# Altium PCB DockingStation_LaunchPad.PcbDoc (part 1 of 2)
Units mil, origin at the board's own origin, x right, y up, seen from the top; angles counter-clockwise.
Board outline 5425 x 6950 mil, 4 copper layers (Top Layer, GND, Power, Bottom Layer), stack 58.4 mil thick; 172 components, 183 nets, 692 pads, 746 vias.
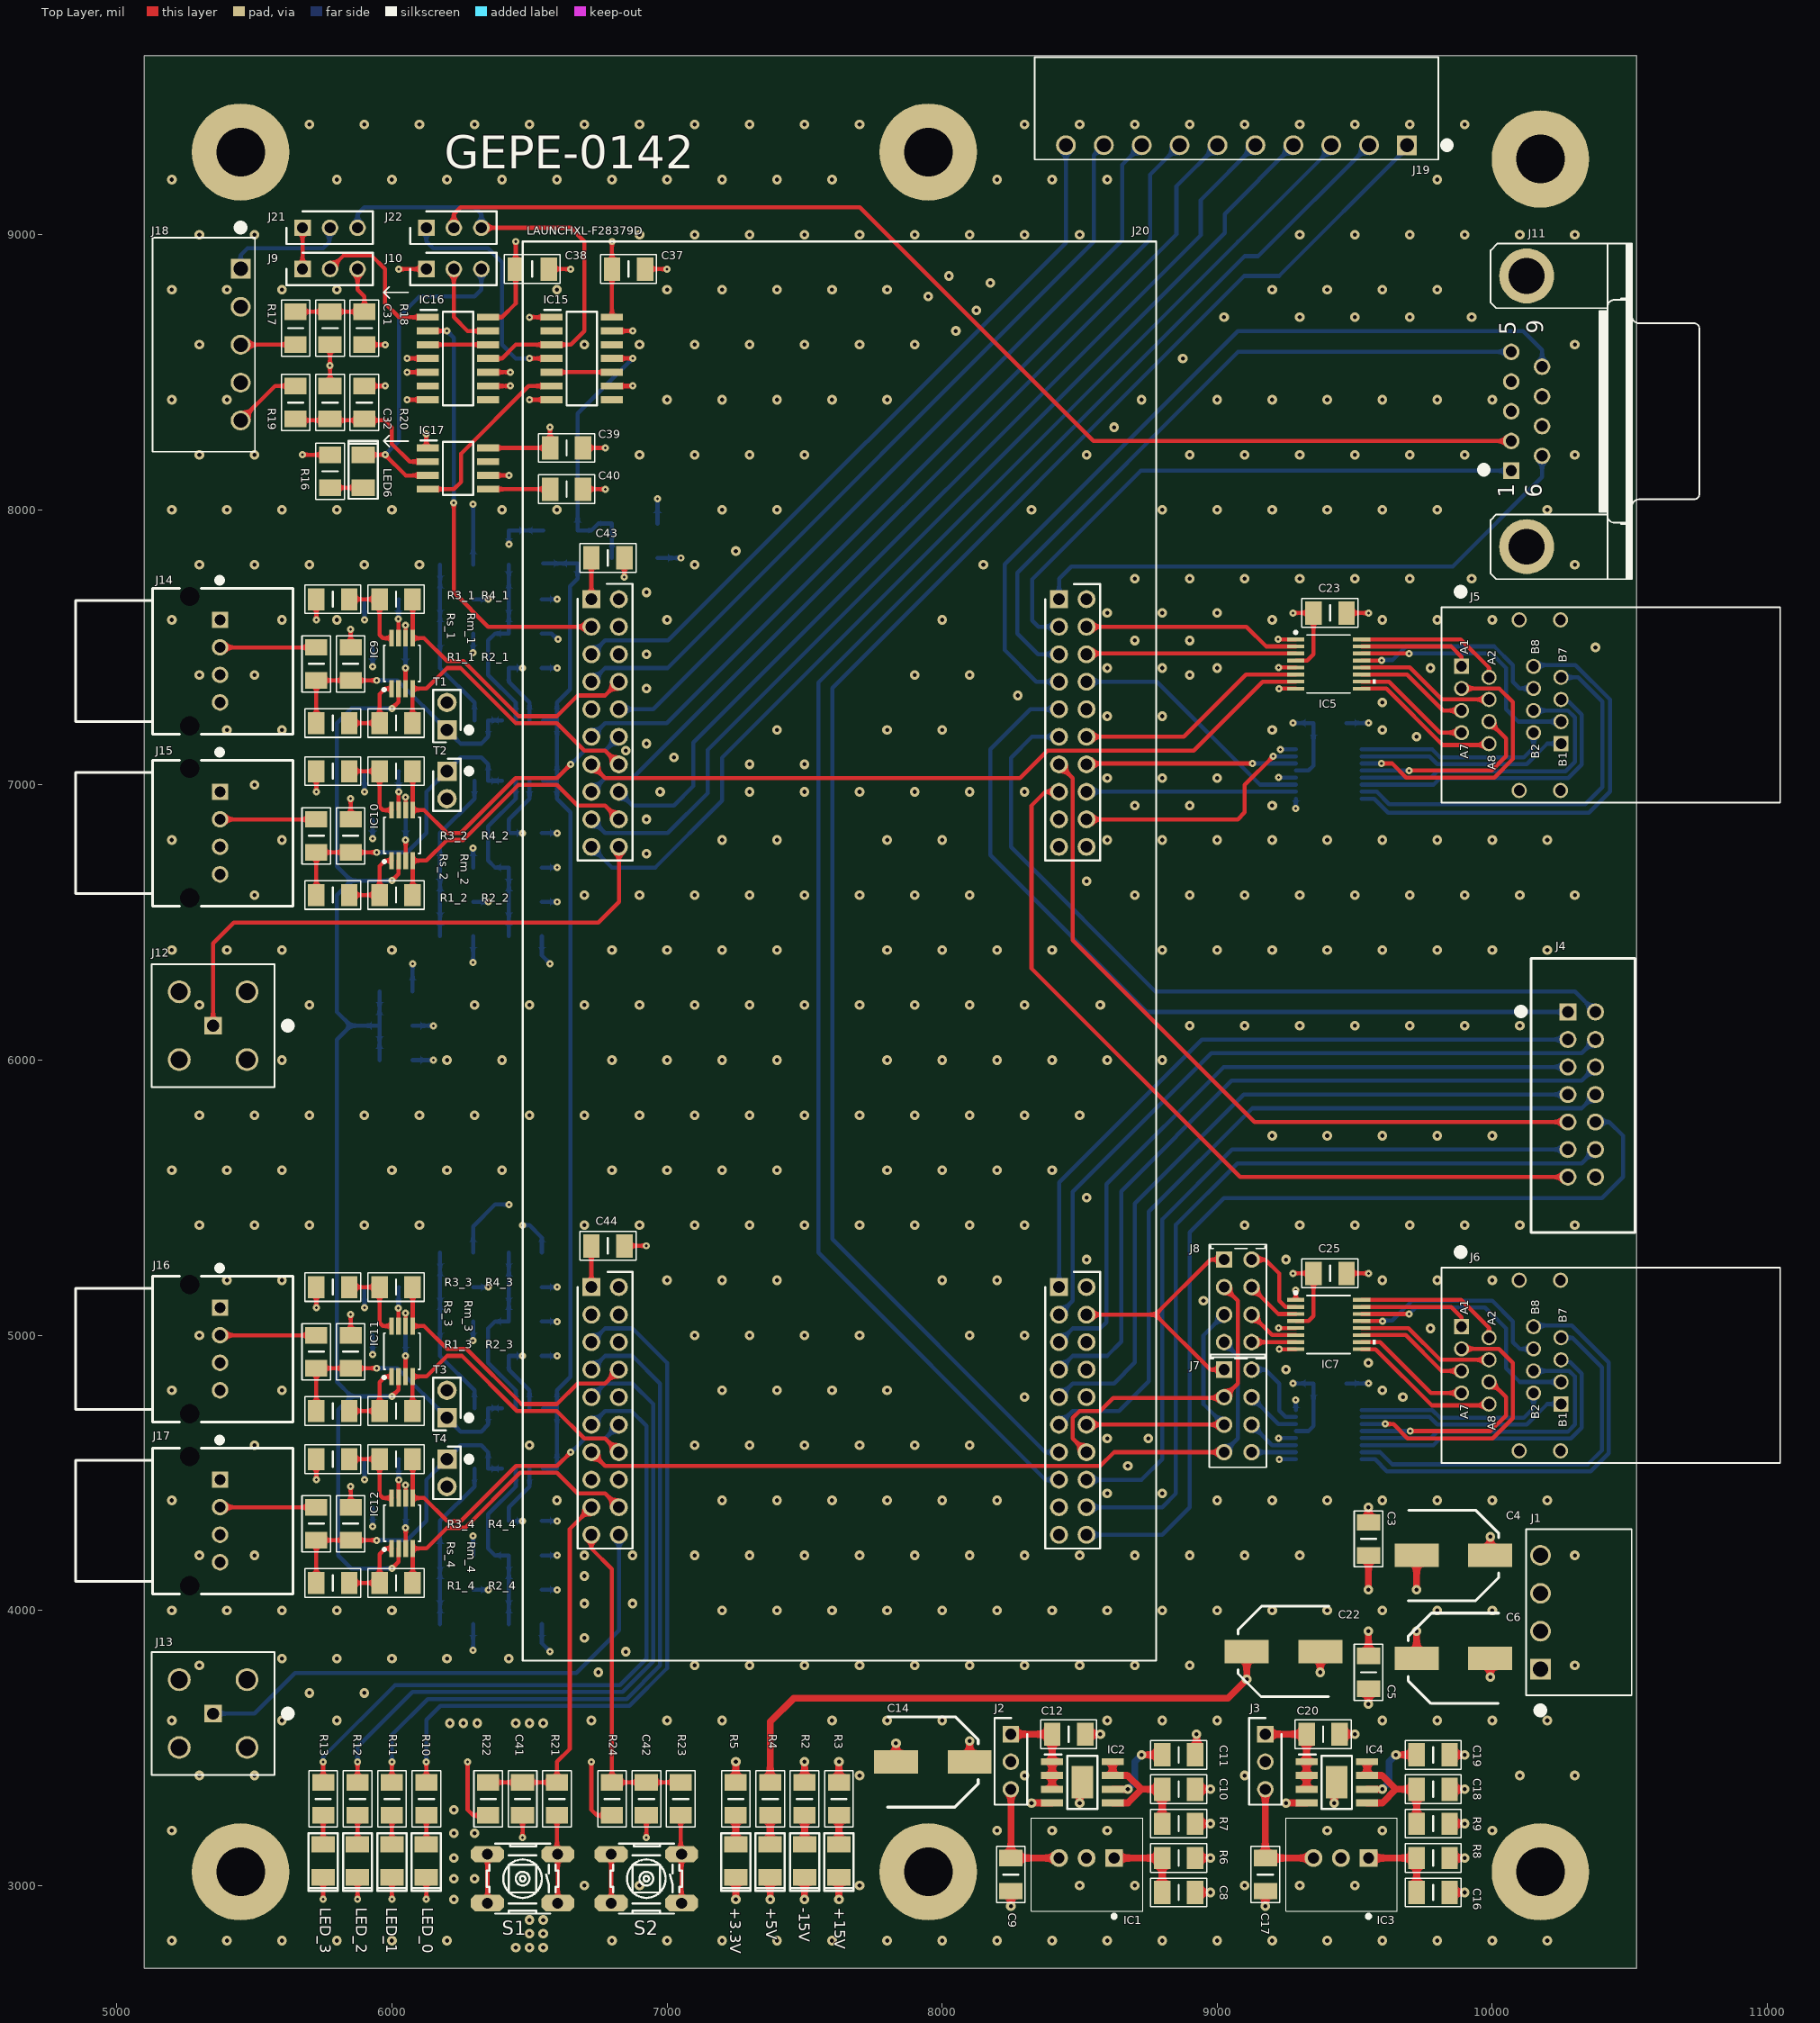
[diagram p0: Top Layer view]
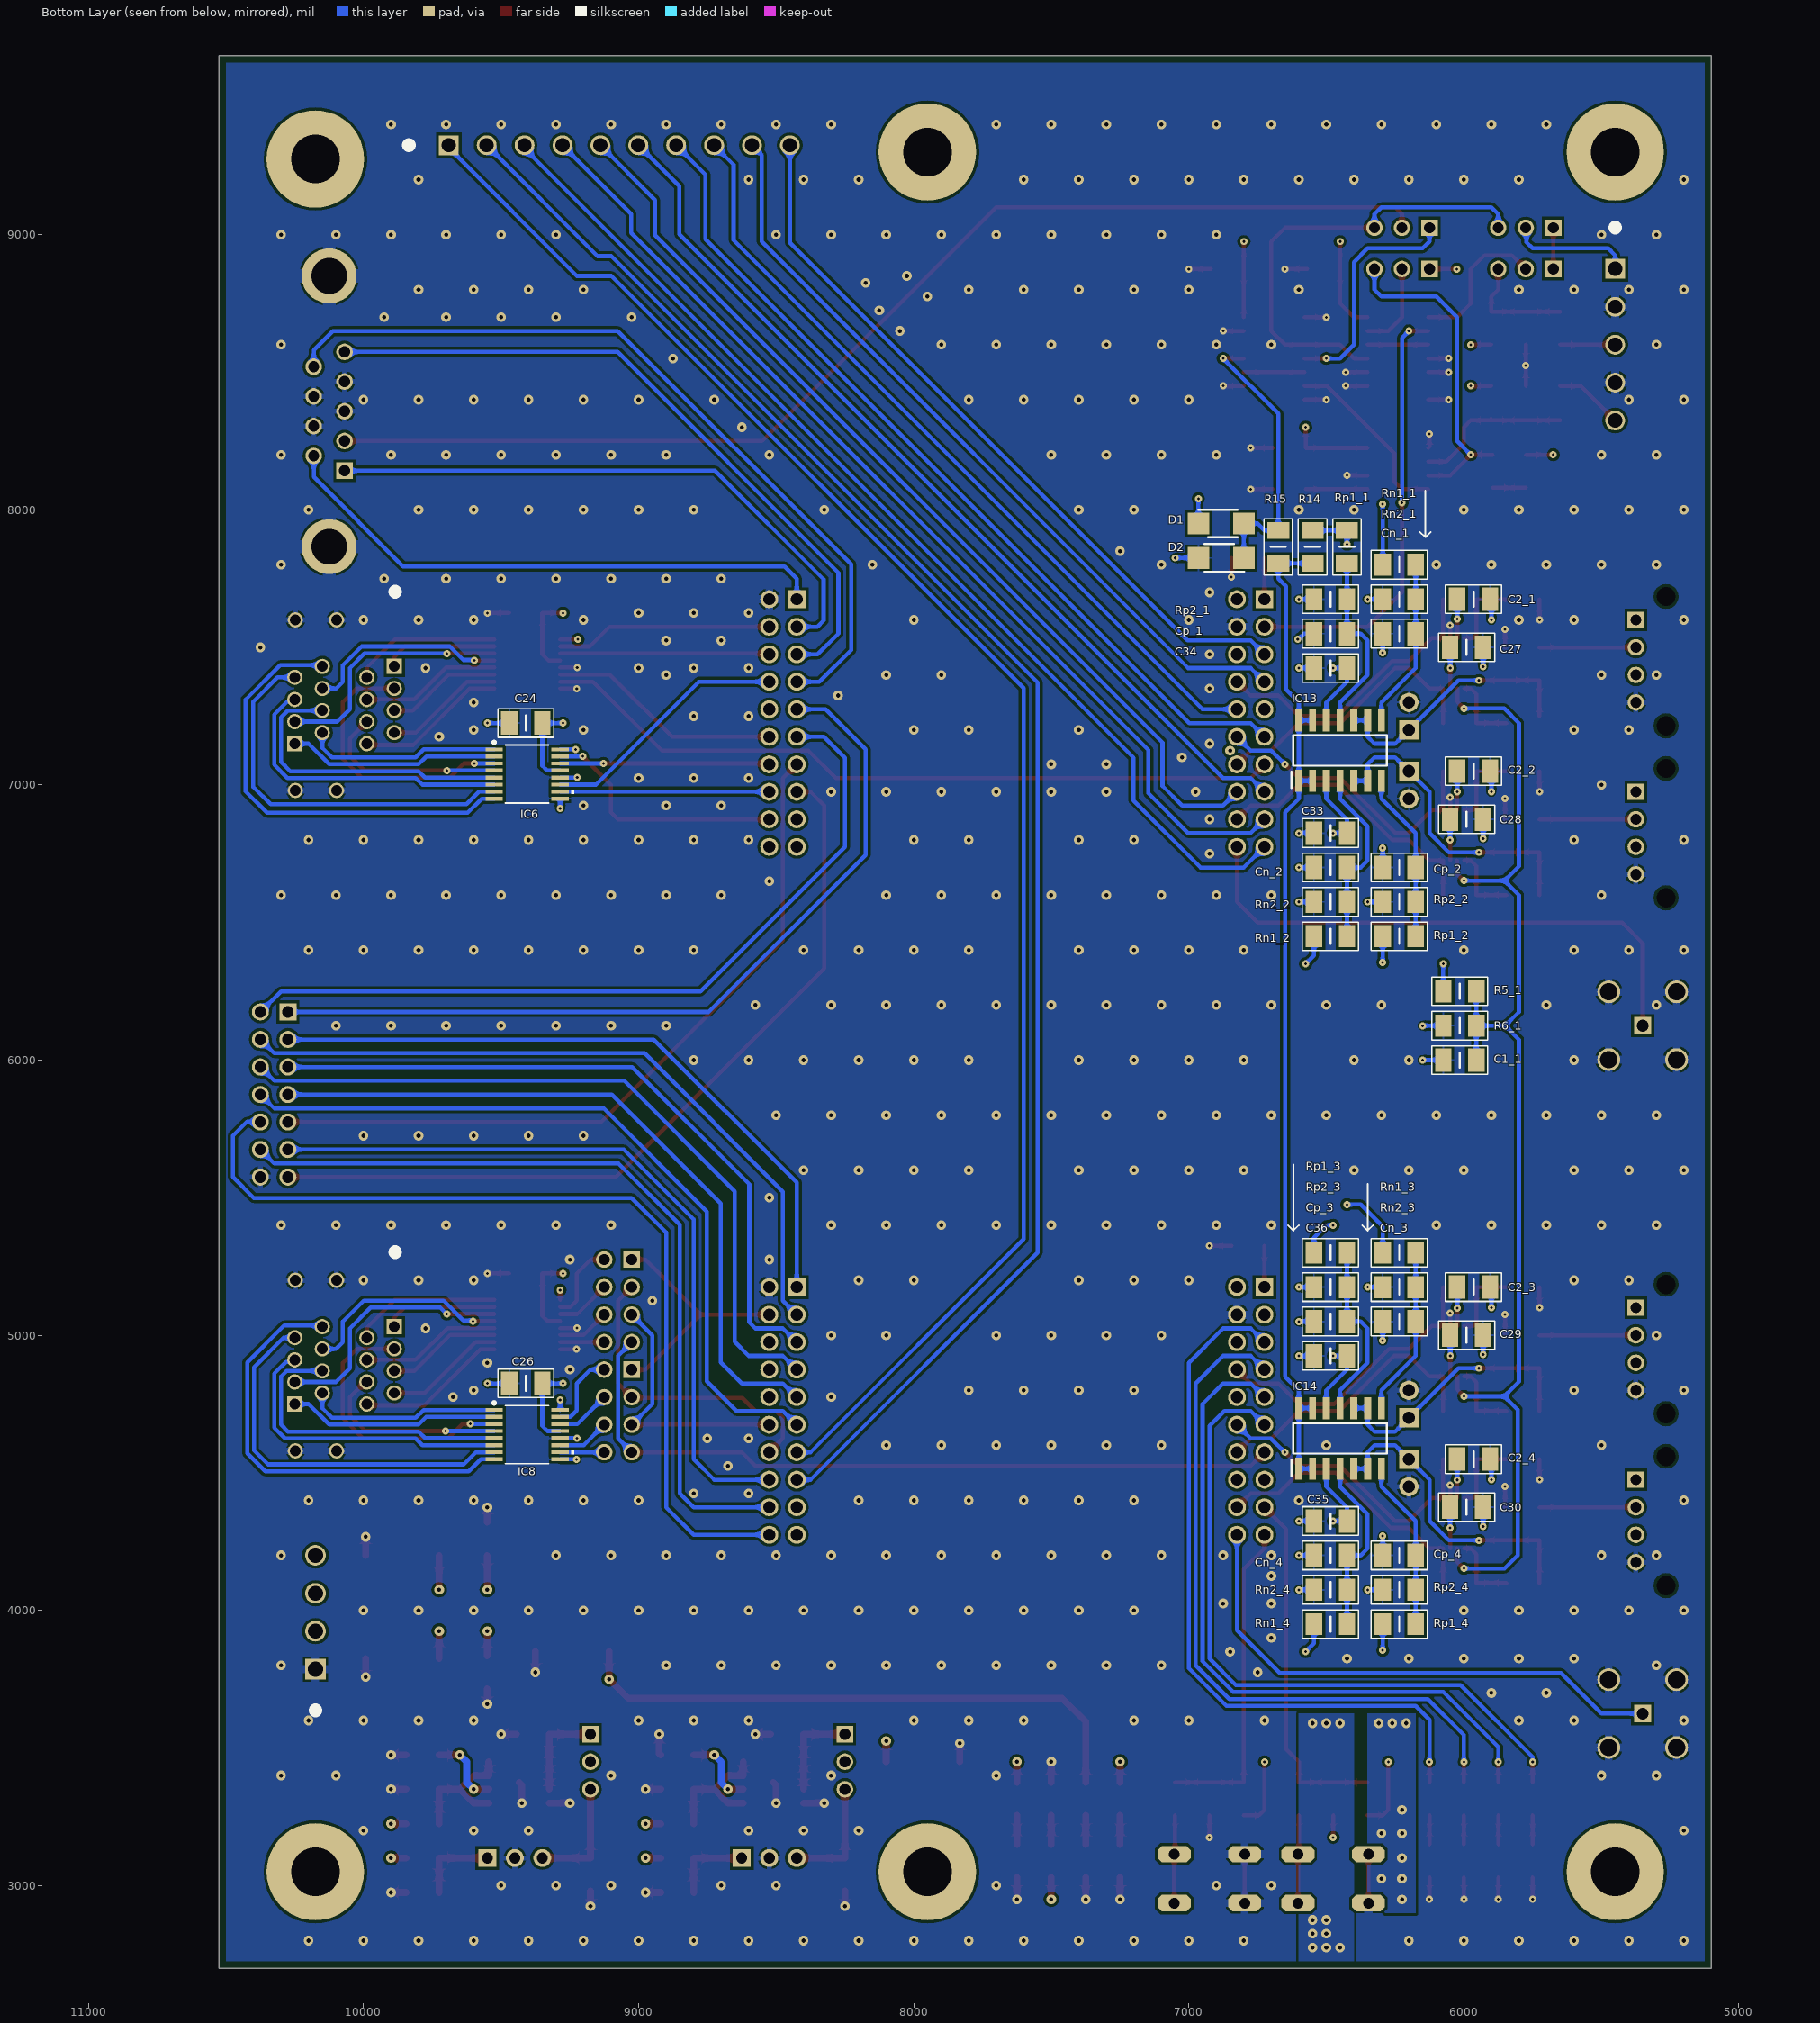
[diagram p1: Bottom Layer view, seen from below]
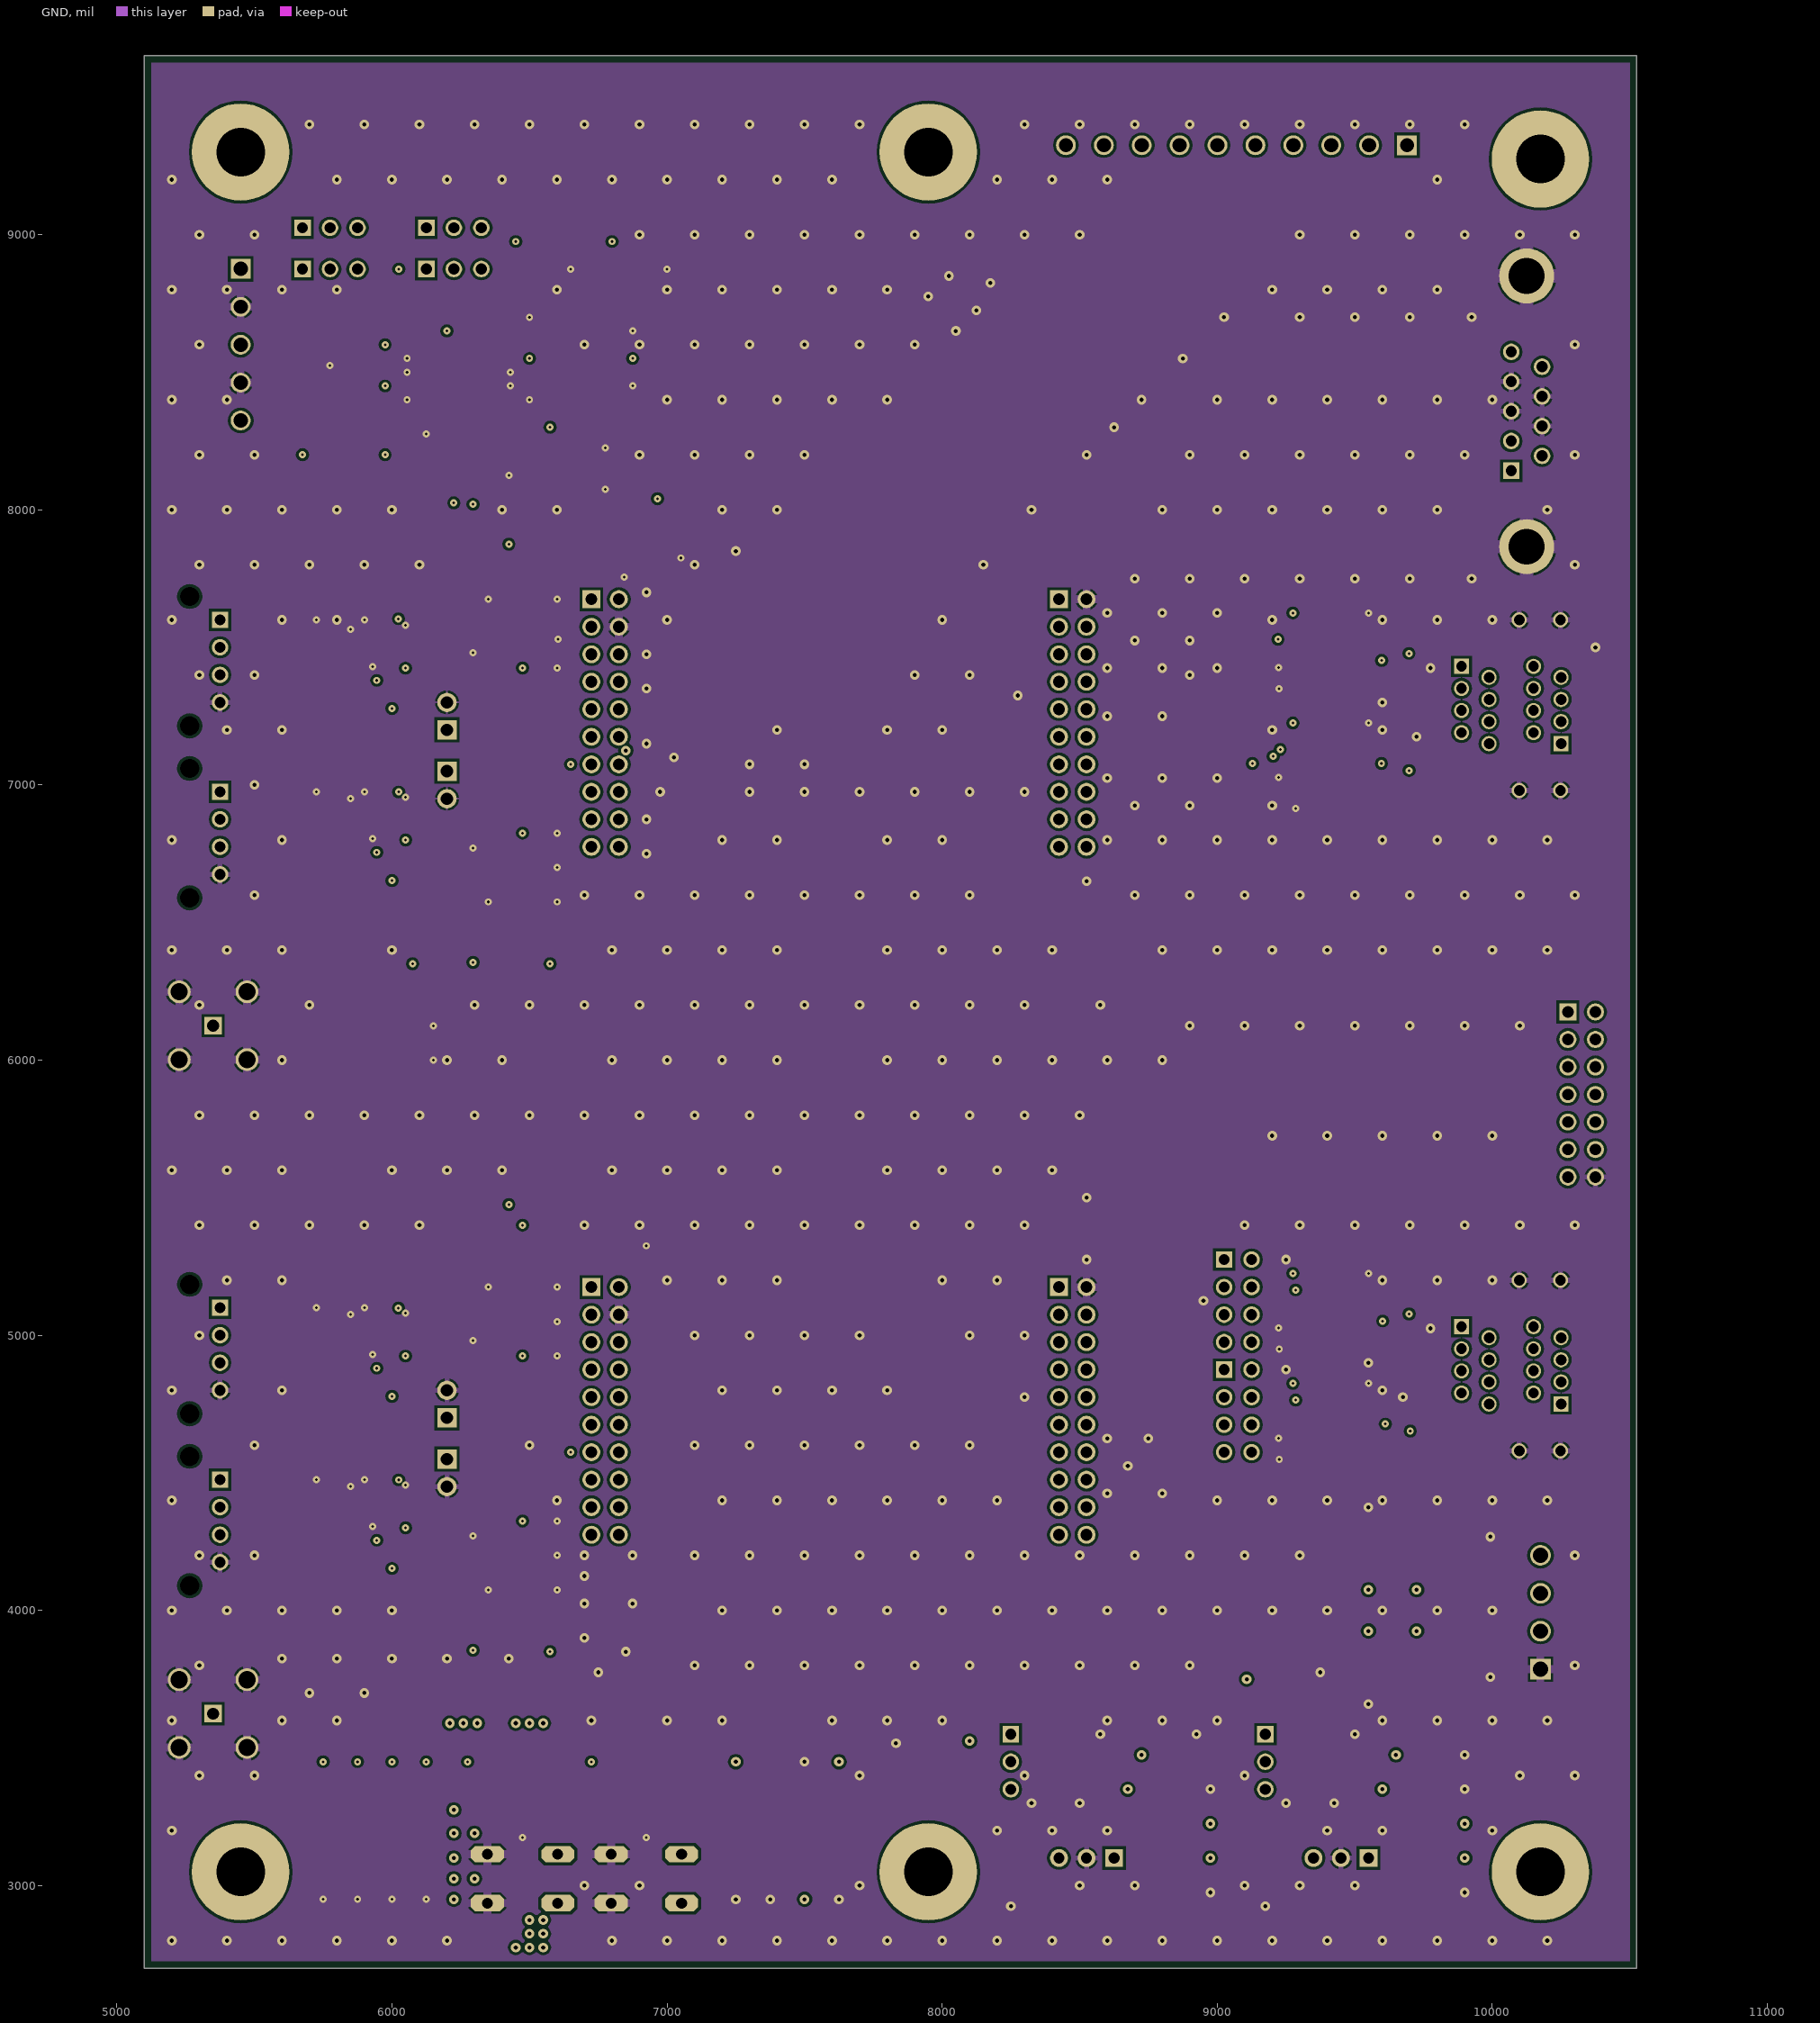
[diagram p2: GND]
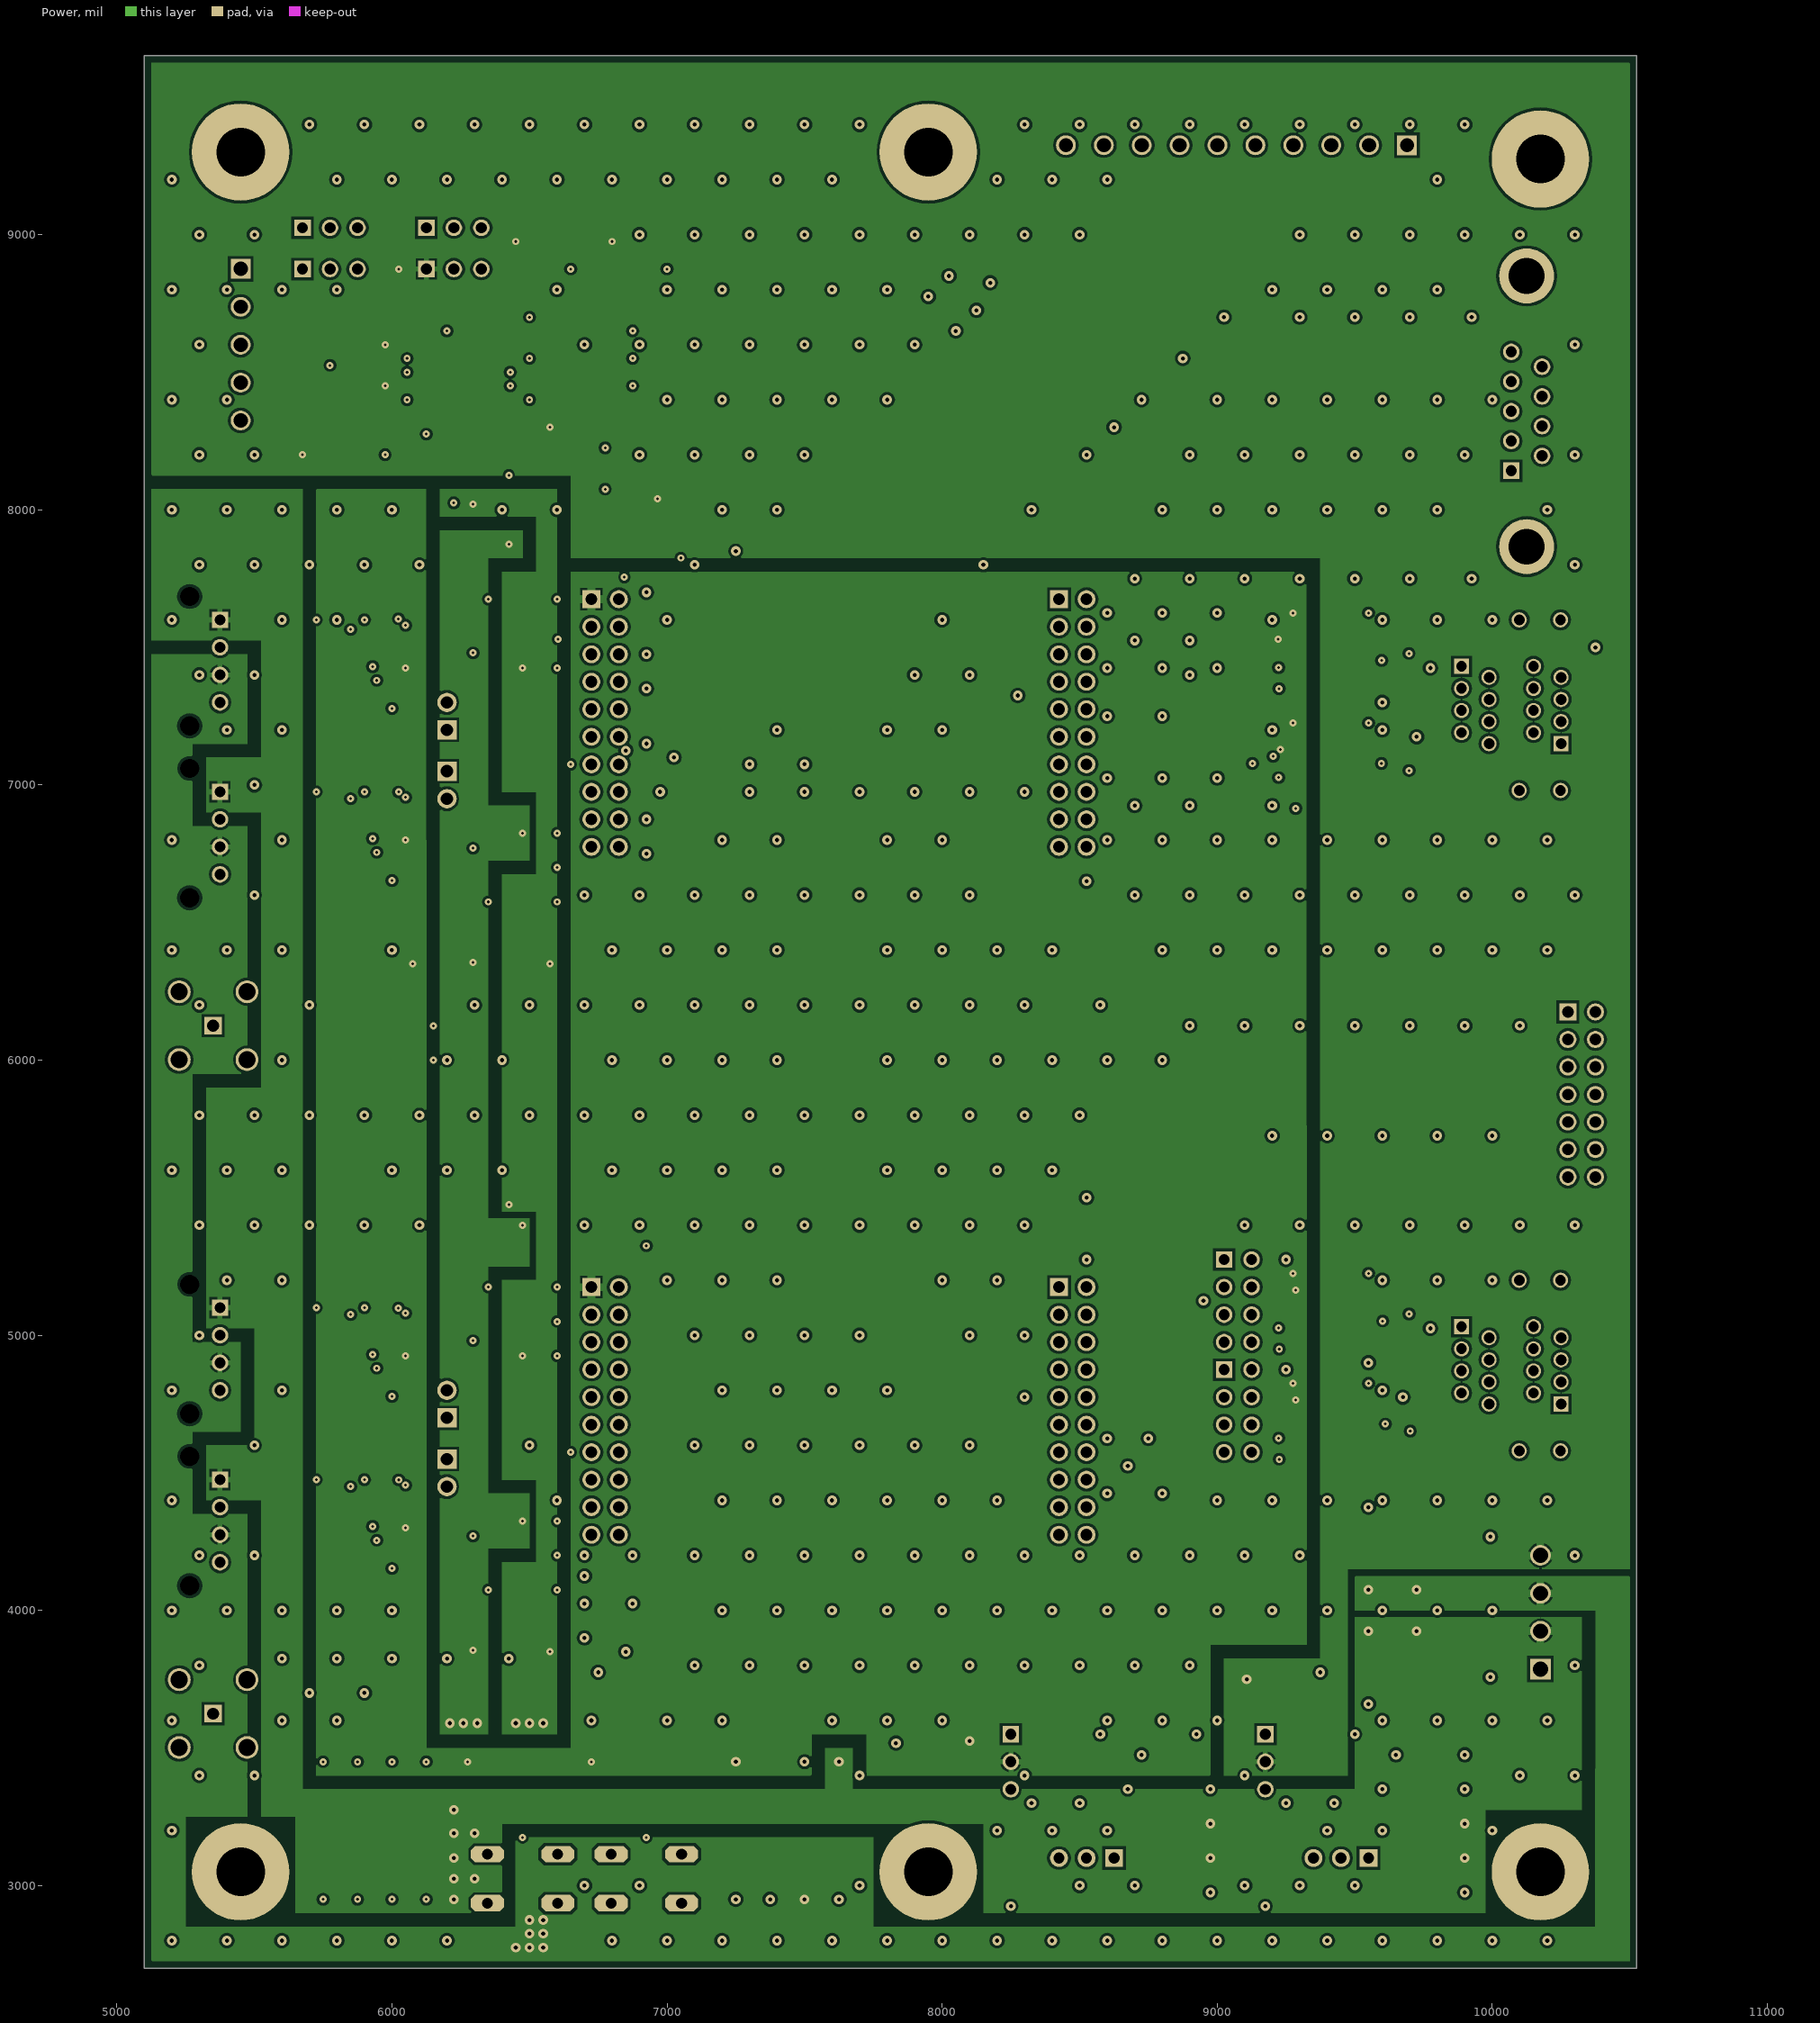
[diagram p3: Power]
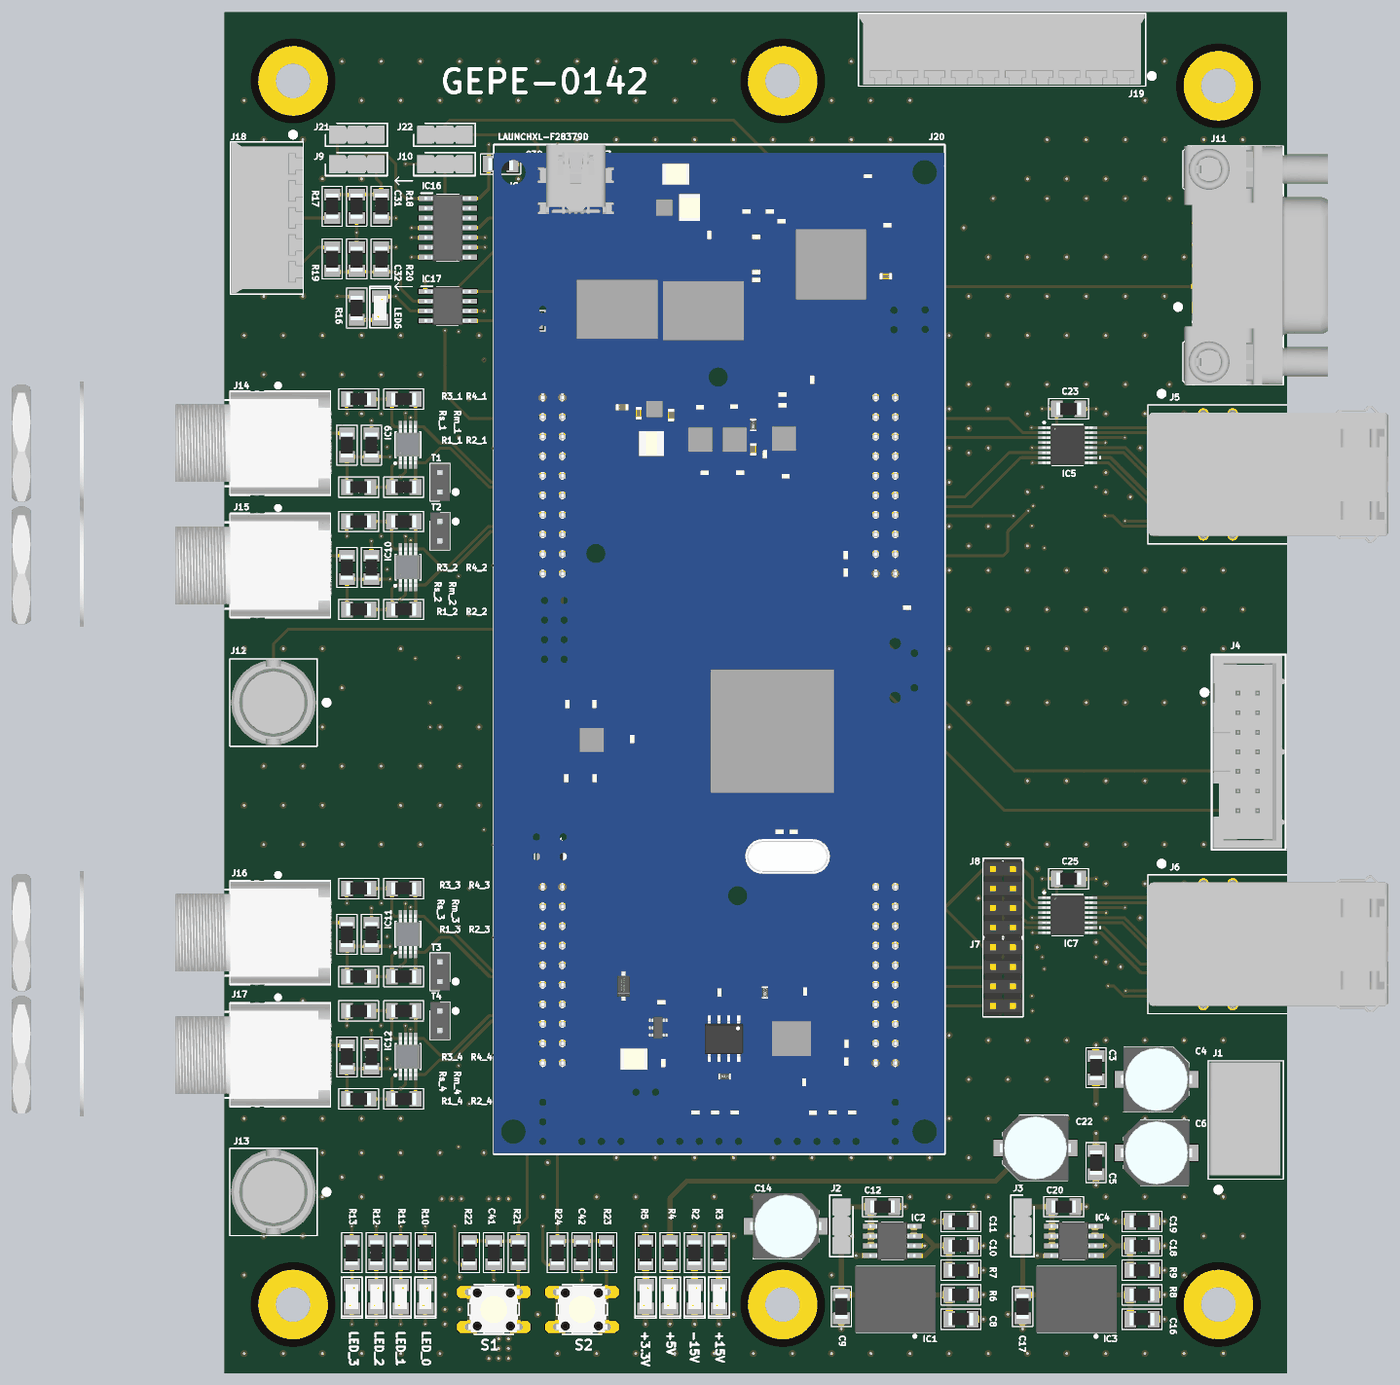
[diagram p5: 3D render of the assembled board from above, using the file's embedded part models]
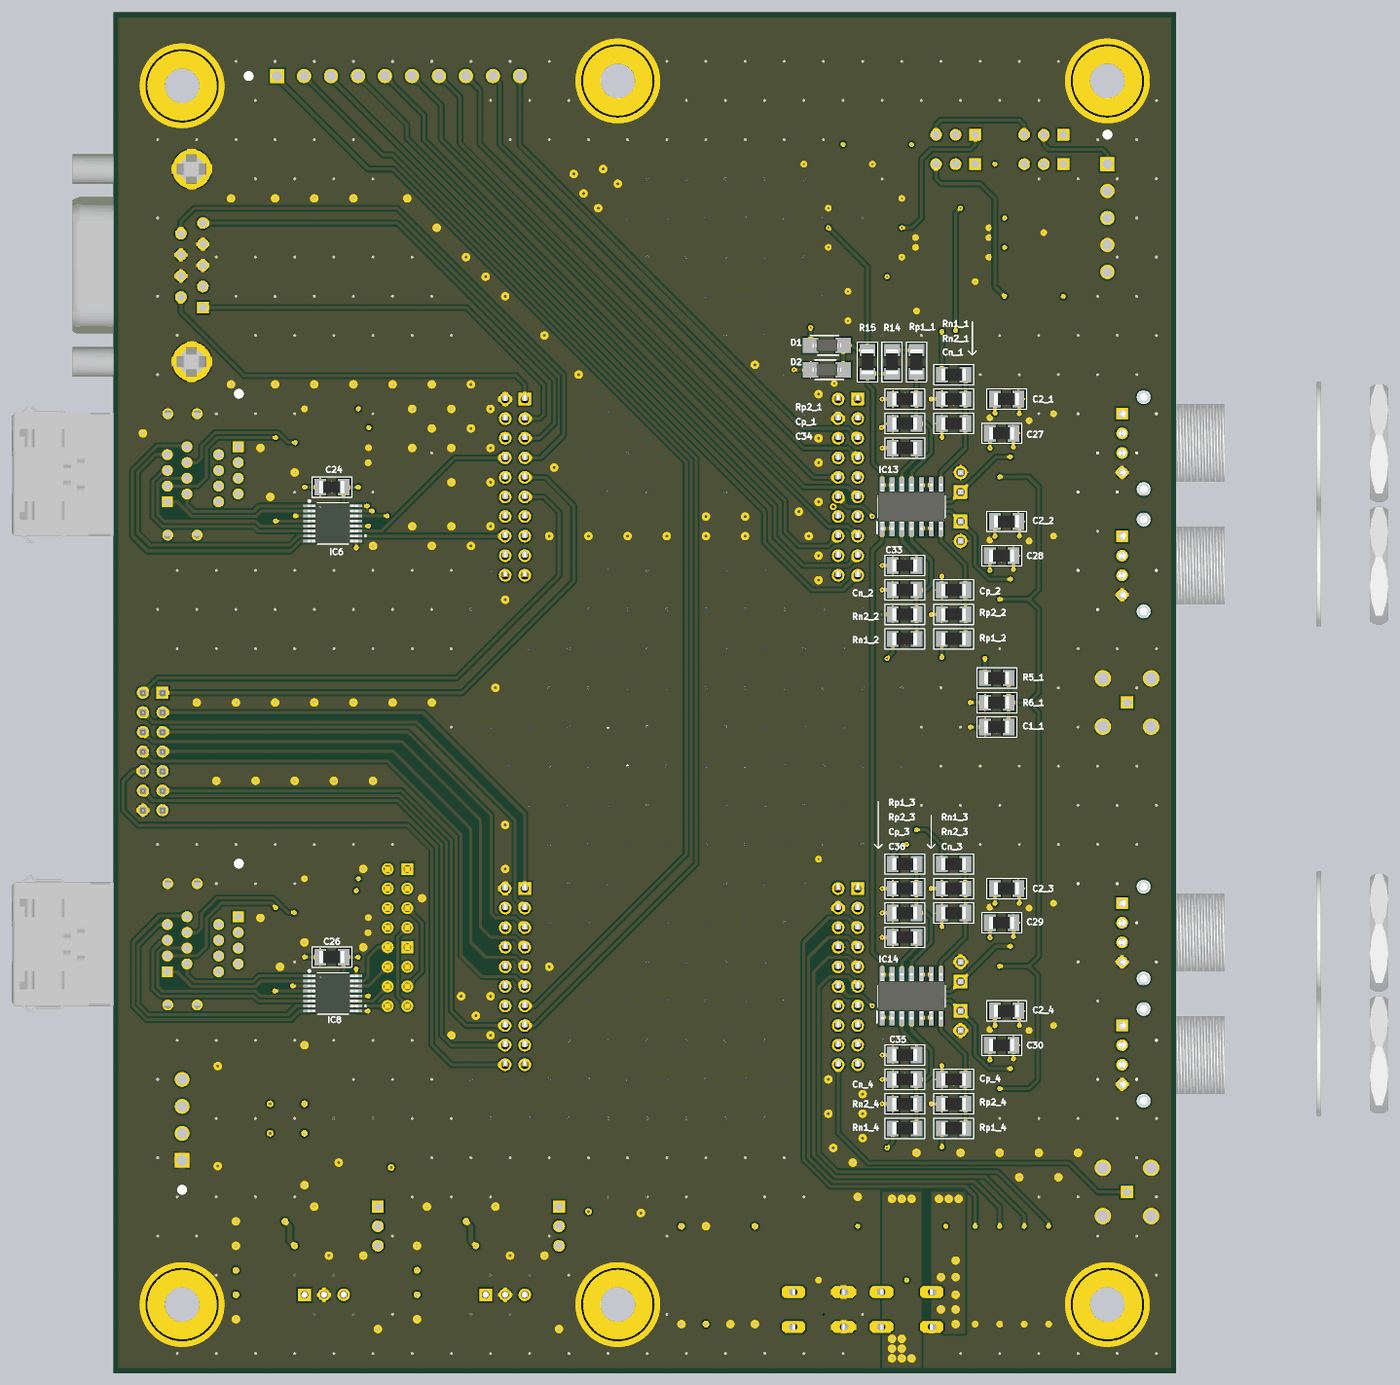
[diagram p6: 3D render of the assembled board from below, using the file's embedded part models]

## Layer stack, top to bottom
Top Solder: solder mask 0.4, Solder Resist, Dk 3.5
Top Layer: signal copper 1.4
Dielectric 2: prepreg 2.8, PP-006, Dk 4.29
GND: signal copper 1.378
Dielectric 1: dielectric 47.2441, FR-4, Dk 4.8
Power: signal copper 1.378
Dielectric 3: prepreg 2.8, PP-006, Dk 4.29
Bottom Layer: signal copper 1.4
Bottom Solder: solder mask 0.4, Solder Resist, Dk 3.5

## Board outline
10525,2700 5100,2700 5100,9650 10525,9650

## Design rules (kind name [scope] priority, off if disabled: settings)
Clearance [All] p1: gap=5 ignorepadtopadclearanceinfootprint=FALSE
ComponentClearance [All] p1: gap=0 collisioncheckmode=3 verticalgap=0 showdistances=FALSE
Height [All] p1: minheight=0 maxheight=2000 prefheight=500
HoleSize [All] p1: absolutevalues=TRUE maxlimit=200 minlimit=1 maxpercent=80.000 minpercent=20.000
MinimumAnnularRing [All] p1: minimumring=8
MinimumSolderMaskSliver [All] p1: minsoldermaskwidth=0
PolygonConnect PolygonConnect-xTW [All] p1: connectstyle=Relief reliefconductorwidth=7.87 reliefentries=4 polygonreliefangle="90 Angle" airgapwidth=7.87
RoutingVias [All] p1: holewidth=10 width=20 viastyle="Through Hole" minholewidth=10 minwidth=20 maxholewidth=28 maxwidth=50
SilkToSilkClearance [All] p1: silktosilkclearance=0
SilkToSolderMaskClearance [IsPad] p1: minsilkscreentomaskgap=0 clearancetoexposedcopper=TRUE
SolderMaskExpansion [All] p1: expansion=4
Width [All] p1: maxlimit=25 minlimit=15 preferedwidth=15
24 further rules are at their usual default settings.

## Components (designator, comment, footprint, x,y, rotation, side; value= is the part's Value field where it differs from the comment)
+3.3V "TLHR5400-AS12Z" LED_SMD_1206 7250,3090 r90 top
+5V "TLHR5400-AS12Z" LED_SMD_1206 7375,3090 r90 top
+15V "TLHR5400-AS12Z" LED_SMD_1206 7625,3090 r90 top
-15V "TLHR5400-AS12Z" LED_SMD_1206 7500,3090 r90 top
C1_1 "CAP" CAP1206_SMD 6015,6000 r0 bottom
C2_1 "CAP" CAP1206_SMD 5965,7675 r180 bottom
C2_2 "CAP" CAP1206_SMD 5965,7050 r180 bottom
C2_3 "CAP" CAP1206_SMD 5965,5175 r180 bottom
C2_4 "CAP" CAP1206_SMD 5965,4550 r180 bottom
C3 "CAP" CAP1206_SMD 9550,4260 r270 top
C4 "CAP" CAP_ELETRO_SMD_6.8 9858.86,4200 r180 top
C5 "CAP" CAP1206_SMD 9550,3775 r270 top
C6 "CAP" CAP_ELETRO_SMD_6.8 9858.86,3825 r0 top
C8 "CAP" CAP1206_SMD 8860,2975 r0 top
C9 "CAP" CAP1206_SMD 8250,3040 r270 top
C10 "CAP" CAP1206_SMD 8860,3350 r0 top
C11 "CAP" CAP1206_SMD 8860,3475 r0 top
C12 "CAP" CAP1206_SMD 8460,3550 r0 top
C14 "CAP" CAP_ELETRO_SMD_6.8 7966.14,3450 r180 top
C16 "CAP" CAP1206_SMD 9785,2975 r0 top
C17 "CAP" CAP1206_SMD 9175,3040 r270 top
C18 "CAP" CAP1206_SMD 9785,3350 r0 top
C19 "CAP" CAP1206_SMD 9785,3475 r0 top
C20 "CAP" CAP1206_SMD 9385,3550 r0 top
C22 "CAP" CAP_ELETRO_SMD_6.8 9241.14,3850 r0 top
C23 "CAP" CAP1206_SMD 9410,7625 r0 top
C24 "CAP" CAP1206_SMD 9410,7225 r0 bottom
C25 "CAP" CAP1206_SMD 9410,5225 r0 top
C26 "CAP" CAP1206_SMD 9410,4825 r0 bottom
C27 "CAP" CAP1206_SMD 5990,7500 r180 bottom
C28 "CAP" CAP1206_SMD 5990,6875 r180 bottom
C29 "CAP" CAP1206_SMD 5990,5000 r180 bottom
C30 "CAP" CAP1206_SMD 5990,4375 r180 bottom
C31 "CAP" CAP1206_SMD 5775,8660 r270 top
C32 "CAP" CAP1206_SMD 5775,8390 r90 top
C33 "CAP" CAP1206_SMD 6485,6825 r0 bottom
C34 "CAP" CAP1206_SMD 6485,7425 r180 bottom
C35 "CAP" CAP1206_SMD 6485,4325 r0 bottom
C36 "CAP" CAP1206_SMD 6485,4925 r180 bottom
C37 "CAP" CAP1206_SMD 6860,8875 r0 top
C38 "CAP" CAP1206_SMD 6510,8875 r0 top
C39 "CAP" CAP1206_SMD 6635,8225 r0 top
C40 "CAP" CAP1206_SMD 6635,8075 r0 top
C41 "CAP" CAP1206_SMD 6475,3315 r270 top
C42 "CAP" CAP1206_SMD 6925,3315 r270 top
C43 "CAP" CAP1206_SMD 6785,7825 r0 top
C44 "CAP" CAP1206_SMD 6785,5325 r0 top
Cn_1 "CAP" CAP1206_SMD 6235,7550 r0 bottom
Cn_2 "CAP" CAP1206_SMD 6485,6700 r0 bottom
Cn_3 "CAP" CAP1206_SMD 6235,5050 r0 bottom
Cn_4 "CAP" CAP1206_SMD 6485,4200 r0 bottom
Cp_1 "CAP" CAP1206_SMD 6485,7550 r0 bottom
Cp_2 "CAP" CAP1206_SMD 6235,6700 r0 bottom
Cp_3 "CAP" CAP1206_SMD 6485,5050 r0 bottom
Cp_4 "CAP" CAP1206_SMD 6235,4200 r0 bottom
D1 "TLHR5400-AS12Z" DIODE_SMD_SOD123 6882.68,7950 r180 bottom
D2 "TLHR5400-AS12Z" DIODE_SMD_SOD123 6882.68,7825 r0 bottom
IC1 "OKI-78SR-3.3_1.5-W36-C" REG_TH_3P_2.54 8525,3088.19 r180 top
IC2 "ADP7118ARDZ-3.3" IC_SMD_SOIC08_THERMAL 8510,3375 r0 top
IC3 "OKI-78SR-3.3_1.5-W36-C" REG_TH_3P_2.54 9450,3088.19 r180 top
IC4 "ADP7118ARDZ-3.3" IC_SMD_SOIC08_THERMAL 9435,3375 r0 top
IC5 "MAX9123" MAX91XX 9405.25,7439.57 r0 top
IC6 "MAX91221/22" MAX91XX 9405.25,7039.57 r180 bottom
IC7 "MAX9123" MAX91XX 9405.25,5038.98 r0 top
IC8 "MAX91221/22" MAX91XX 9405.25,4638.98 r180 bottom
IC9 "LTC1992" LTC1992 6036.61,7441.75 r90 top
IC10 "LTC1992" LTC1992 6037.2,6816.75 r90 top
IC11 "LTC1992" LTC1992 6036.61,4941.75 r90 top
IC12 "LTC1992" LTC1992 6037.2,4316.75 r90 top
IC13 "LM339AN" IC_SMD_SOIC14 6450,7125 r90 bottom
IC14 "LM339AN" IC_SMD_SOIC14 6450,4625 r90 bottom
IC15 "Not Gate" IC_SMD_SOIC14 6690,8550 r0 top
IC16 "SN7400N" IC_SMD_SOIC14 6240,8550 r0 top
IC17 "NE555N" IC_SMD_SOIC08 6240,8150 r0 top
J1 "2350514-4" CON_4PIN_HORIZONTAL_3.5MM 10175,3786.61 r90 top
J2 "22-27-2031" HEADER_MALE_TH_3P_2.54 8250,3550 r90 top
J3 "22-27-2031" HEADER_MALE_TH_3P_2.54 9175,3550 r90 top
J4 "Header 7X2" HEADER_2R_14P 10274,6175 r270 top
J5 "1888652-1" CON_ETHERNET_2X1 9888.19,7431.1 r90 top
J6 "1888652-1" CON_ETHERNET_2X1 9888.19,5031.1 r90 top
J7 "826656-4" HEADER_MALE_TH_8P_2R-2.54 9025,4875 r270 top
J8 "826656-4" HEADER_MALE_TH_8P_2R-2.54 9025,5275 r270 top
J9 "22-27-2031" HEADER_MALE_TH_3P_2.54 5675,8875 r180 top
J10 "22-27-2031" HEADER_MALE_TH_3P_2.54 6125,8875 r180 top
J11 "Con_DB9" CON_DB9_MALE 10069,8574 r90 top
J12 "5-1634503-1" CON_BNC_5-1634503-1 5350,6125 r0 top
J13 "5-1634503-1" CON_BNC_5-1634503-1 5350,3625 r0 top
J14 "Con_MiniXLR_TRAPC4M" CON_MINIXLR_TRAPC4M1X 5375,7600 r270 top
J15 "Con_MiniXLR_TRAPC4M" CON_MINIXLR_TRAPC4M1X 5375,6975 r270 top
J16 "Con_MiniXLR_TRAPC4M" CON_MINIXLR_TRAPC4M1X 5375,5100 r270 top
J17 "Con_MiniXLR_TRAPC4M" CON_MINIXLR_TRAPC4M1X 5375,4475 r270 top
J18 "284512-5" Con_5Pin_Horizontal_3.5mm 5450,8875.59 r270 top
J19 "1-284512-0" CON_10PIN_HORIZONTAL_PLUGIN_3.50MM 9690.16,9325 r180 top
J20 "Con_Header_LaunchPad_F28379D" LAUNCHPAD_F28379D 6475,8975 r270 top
J21 "22-27-2031" HEADER_MALE_TH_3P_2.54 5675,9025 r180 top
J22 "22-27-2031" HEADER_MALE_TH_3P_2.54 6125,9025 r180 top
LED6 "TLHR5400-AS12Z" LED_SMD_1206 5895,8140 r270 top
LED_0 "TLHR5400-AS12Z" LED_SMD_1206 6125,3090 r90 top
LED_1 "TLHR5400-AS12Z" LED_SMD_1206 6000,3090 r90 top
LED_2 "TLHR5400-AS12Z" LED_SMD_1206 5875,3090 r90 top
LED_3 "TLHR5400-AS12Z" LED_SMD_1206 5750,3090 r90 top
R1_1 "Res1" RESIS_SMD_1206 5785,7225 r180 top
R1_2 "Res1" RESIS_SMD_1206 5785,6600 r180 top
R1_3 "Res1" RESIS_SMD_1206 5785,4725 r180 top
R1_4 "Res1" RESIS_SMD_1206 5785,4100 r180 top
R2 "Res1" RESIS_SMD_1206 7500,3315 r90 top
R2_1 "Res1" RESIS_SMD_1206 6015,7225 r180 top
R2_2 "Res1" RESIS_SMD_1206 6015,6600 r180 top
R2_3 "Res1" RESIS_SMD_1206 6015,4725 r180 top
R2_4 "Res1" RESIS_SMD_1206 6015,4100 r180 top
R3 "Res1" RESIS_SMD_1206 7625,3315 r270 top
R3_1 "Res1" RESIS_SMD_1206 5785,7675 r180 top
R3_2 "Res1" RESIS_SMD_1206 5785,7050 r180 top
R3_3 "Res1" RESIS_SMD_1206 5785,5175 r180 top
R3_4 "Res1" RESIS_SMD_1206 5785,4550 r180 top
R4 "Res1" RESIS_SMD_1206 7375,3315 r270 top
R4_1 "Res1" RESIS_SMD_1206 6015,7675 r0 top
R4_2 "Res1" RESIS_SMD_1206 6015,7050 r0 top
R4_3 "Res1" RESIS_SMD_1206 6015,5175 r0 top
R4_4 "Res1" RESIS_SMD_1206 6015,4550 r0 top
R5 "Res1" RESIS_SMD_1206 7250,3315 r270 top
R5_1 "Res1" RESIS_SMD_1206 6015,6250 r180 bottom
R6 "Res1" RESIS_SMD_1206 8860,3100 r180 top
R6_1 "Res1" RESIS_SMD_1206 6015,6125 r0 bottom
R7 "Res1" RESIS_SMD_1206 8860,3225 r0 top
R8 "Res1" RESIS_SMD_1206 9785,3100 r180 top
R9 "Res1" RESIS_SMD_1206 9785,3225 r0 top
R10 "Res1" RESIS_SMD_1206 6125,3315 r270 top
R11 "Res1" RESIS_SMD_1206 6000,3315 r270 top
R12 "Res1" RESIS_SMD_1206 5875,3315 r270 top
R13 "Res1" RESIS_SMD_1206 5750,3315 r270 top
R14 "Res1" RESIS_SMD_1206 6550,7865 r90 bottom
R15 "Res1" RESIS_SMD_1206 6675,7865 r90 bottom
R16 "Res1" RESIS_SMD_1206 5775,8140 r90 top
R17 "Res1" RESIS_SMD_1206 5650,8660 r270 top
R18 "Res1" RESIS_SMD_1206 5900,8660 r270 top
R19 "Res1" RESIS_SMD_1206 5650,8390 r90 top
R20 "Res1" RESIS_SMD_1206 5900,8390 r90 top
R21 "Res1" RESIS_SMD_1206 6600,3315 r270 top
R22 "Res1" RESIS_SMD_1206 6350,3315 r270 top
R23 "Res1" RESIS_SMD_1206 7050,3315 r270 top
R24 "Res1" RESIS_SMD_1206 6800,3315 r270 top
Rm_1 "Res1" RESIS_SMD_1206 5850,7440 r90 top
Rm_2 "Res1" RESIS_SMD_1206 5850,6815 r90 top
Rm_3 "Res1" RESIS_SMD_1206 5850,4940 r90 top
Rm_4 "Res1" RESIS_SMD_1206 5850,4315 r90 top
Rn1_1 "Res1" RESIS_SMD_1206 6235,7800 r0 bottom
Rn1_2 "Res1" RESIS_SMD_1206 6485,6450 r0 bottom
Rn1_3 "Res1" RESIS_SMD_1206 6235,5300 r0 bottom
Rn1_4 "Res1" RESIS_SMD_1206 6485,3950 r0 bottom
Rn2_1 "Res1" RESIS_SMD_1206 6235,7675 r180 bottom
Rn2_2 "Res1" RESIS_SMD_1206 6485,6575 r180 bottom
Rn2_3 "Res1" RESIS_SMD_1206 6235,5175 r180 bottom
Rn2_4 "Res1" RESIS_SMD_1206 6485,4075 r180 bottom
Rp1_1 "Res1" RESIS_SMD_1206 6425,7865 r90 bottom
Rp1_2 "Res1" RESIS_SMD_1206 6235,6450 r0 bottom
Rp1_3 "Res1" RESIS_SMD_1206 6485,5300 r0 bottom
Rp1_4 "Res1" RESIS_SMD_1206 6235,3950 r0 bottom
Rp2_1 "Res1" RESIS_SMD_1206 6485,7675 r180 bottom
Rp2_2 "Res1" RESIS_SMD_1206 6235,6575 r180 bottom
Rp2_3 "Res1" RESIS_SMD_1206 6485,5175 r180 bottom
Rp2_4 "Res1" RESIS_SMD_1206 6235,4075 r180 bottom
Rs_1 "Res1" RESIS_SMD_1206 5725,7440 r270 top
Rs_2 "Res1" RESIS_SMD_1206 5725,6815 r270 top
Rs_3 "Res1" RESIS_SMD_1206 5725,4940 r270 top
Rs_4 "Res1" RESIS_SMD_1206 5725,4315 r270 top
S1 "1-1825910-8" TACTILE-TH-4PIN 6475,3025 r180 top
S2 "1-1825910-8" TACTILE-TH-4PIN 6925,3025 r180 top
T1 "TB004-508-02BE" HEADER_MALE_TH_2P_2.54 6200,7200 r0 top
T2 "TB004-508-02BE" HEADER_MALE_TH_2P_2.54 6200,7050 r180 top
T3 "TB004-508-02BE" HEADER_MALE_TH_2P_2.54 6200,4700 r0 top
T4 "TB004-508-02BE" HEADER_MALE_TH_2P_2.54 6200,4550 r180 top

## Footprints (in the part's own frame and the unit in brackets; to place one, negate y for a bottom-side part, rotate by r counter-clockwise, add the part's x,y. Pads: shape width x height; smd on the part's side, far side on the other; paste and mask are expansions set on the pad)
CAP1206_SMD [mil]
  rect 60x85 smd: 1(-60,0) 2(60,0)
  silkscreen extent -102,-52 102,52, body extent -63,-31 63,31, height 26
CAP_ELETRO_SMD_6.8 [mil]
  rect 160x85 smd: 1(-133.86,0) 2(133.86,0)
  silkscreen extent -165,-163 165,165, body extent -181,-167 181,167, height 413
CON_4PIN_HORIZONTAL_3.5MM [mil]
  rect 75x75 hole 55 mask+0: 1(0,0)
  round 75 hole 55 mask+0: 2(137.8,0) 3(275.59,0) 4(413.39,0)
  silkscreen extent -150,-332 509,52, body extent -75,-316 500,46, height 286
Con_5Pin_Horizontal_3.5mm [mil]
  rect 72x72 hole 52 mask+0: 1(0,0)
  round 72 hole 52 mask+0: 2(137.8,0) 3(275.59,0) 4(413.39,0) 5(551.18,0)
  silkscreen extent -150,-320 664,52, body extent -109,-312 659,50, height 287
CON_10PIN_HORIZONTAL_PLUGIN_3.50MM [mil]
  rect 72x72 hole 52 mask+0: 1(0,0)
  round 72 hole 52 mask+0: 2(137.8,0) 3(275.59,0) 4(413.39,0) 5(551.18,0) 6(688.98,0) 7(826.77,0) 8(964.57,0) 9(1102.36,0) 10(1240.16,0)
  silkscreen extent -145,-320 1353,52, body extent -108,-317 1348,45, height 287
CON_BNC_5-1634503-1 [mil]
  rect 63x63 hole 43 mask+0: 1(0,0)
  round 83 hole 63 mask+0: 2(-123.23,123.23) 3(-123.23,-123.23) 4(123.23,-123.23) 5(123.23,123.23)
  silkscreen extent -223,-223 271,223, body extent -217,-217 217,217, height 550
CON_DB9_MALE [mil] "Connector; D Subminiature; 9 Position; Right Angle; Pitch 1.385 mm"
  rect 60x60 hole 40: 1(-432,0)
  round 60 hole 40: 2(-324,0) 3(-216,0) 4(-108,0) 5(0,0) 6(-378,-112) 7(-270,-112) 8(-162,-112) 9(-54,-112)
  round 200 hole 130: 10(-708,-56) 10(276,-56)
  silkscreen extent -826,-684 395,100, body extent -828,-665 394,67, height 497
CON_ETHERNET_2X1 [mm]
  round 1.4 hole 0.991 mask+0: 18(-11.46,-5.33) 19(-11.46,-9.14) 20(4.29,-5.33) 21(4.29,-9.14) A2(-1.02,-2.54) A3(-2.04,0) A4(-3.06,-2.54) A5(-4.08,0) A6(-5.1,-2.54) A7(-6.12,0) A8(-7.14,-2.54) B2(-6.12,-6.65) B3(-5.1,-9.19) B4(-4.08,-6.65) B5(-3.06,-9.19) B6(-2.04,-6.65) B7(-1.02,-9.19) B8(0,-6.65)
  rect 1.4x1.4 hole 0.991 mask+0: A1(0,0) B1(-7.14,-9.19)
  silkscreen extent -12.59,-29.43 6.88,1.86, body extent -12.46,-29.3 5.34,1.73, height 20.01
CON_MINIXLR_TRAPC4M1X [mil]
  rect 60x60 hole 40: 1(0,0)
  round 60 hole 40: 2(200,0) 3(300,0) 4(100,0)
  round 35 hole 70 unplated: MH1(-85,-110) MH2(385,-110)
  silkscreen extent -144,-525 415,265, body extent -162,-1359 463,271, height 105
DIODE_SMD_SOD123 [mm]
  rect 2x2 smd: 1(-2.1,0) 2(2.1,0)
  silkscreen extent -2.13,-1.27 1.52,1.27, body extent -1.85,-0.77 1.85,0.77, height 1.45
HEADER_2R_14P [mil] "HEader 2Row 14pins 2.54mm"
  rect 62x62 hole 42 mask+3: 1(0,1)
  round 62 hole 42 mask+3: 2(0,101) 3(100,1) 4(100,101) 5(200,1) 6(200,101) 7(300,1) 8(300,101) 9(400,1) 10(400,101) 11(500,1) 12(500,101) 13(600,1) 14(600,101)
  silkscreen extent -195,-170 802,245, body extent -190,-124 794,241, height 368
HEADER_MALE_TH_2P_2.54 [mil]
  rect 70x70 hole 45: 1(0,0)
  round 70 hole 45: 2(0,100)
  silkscreen extent -50,-45 50,145, body extent -50,-45 50,145, height 338
HEADER_MALE_TH_3P_2.54 [mil]
  rect 60x60 hole 40: 1(0,0)
  round 60 hole 40: 2(-100,0) 3(-200,0)
  silkscreen extent -256,-59 59,59, body extent -242,-46 42,46, height 328
HEADER_MALE_TH_8P_2R-2.54 [mil]
  rect 60x60 hole 40 mask+0: 1(0,0)
  round 60 hole 40 mask+0: 2(0,100) 3(100,0) 4(100,100) 5(200,0) 6(200,100) 7(300,0) 8(300,100)
  silkscreen extent -55,-54 355,154, body extent -50,-50 350,150, height 374
IC_SMD_SOIC08 [mil]
  rect 80x25.59 smd: 1(-110,75) 2(-110,25) 3(-110,-25) 4(-110,-75) 5(110,-75) 6(110,-25) 7(110,25) 8(110,75)
  silkscreen extent -137,-96 55,102, body extent -118,-96 118,96, height 69
IC_SMD_SOIC08_THERMAL [mil]
  rect 80x25.59 smd: 1(-110,75) 2(-110,25) 3(-110,-25) 4(-110,-75) 5(110,-75) 6(110,-25) 7(110,25) 8(110,75)
  rect 78.74x118.11 smd: 9(-0.24,0.2)
  silkscreen extent -137,-96 55,102, body extent -118,-96 118,96, height 69
IC_SMD_SOIC14 [mil]
  rect 80x25.59 smd: 1(-110,150) 2(-110,100) 3(-110,50) 4(-110,0) 5(-110,-50) 6(-110,-100) 7(-110,-150) 8(110,-150) 9(110,-100) 10(110,-50) 11(110,0) 12(110,50) 13(110,100) 14(110,150)
  silkscreen extent -137,-170 55,177, body extent -118,-170 118,170, height 69
LAUNCHPAD_F28379D [mm]
  rect 1.65x1.65 hole 1.1: 1(33.02,6.35) 40(33.02,49.53) 41(96.52,6.35) 80(96.52,49.53)
  round 1.65 hole 1.1: 2(35.56,6.35) 3(38.1,6.35) 4(40.64,6.35) 5(43.18,6.35) 6(45.72,6.35) 7(48.26,6.35) 8(50.8,6.35) 9(53.34,6.35) 10(55.88,6.35) 11(55.88,52.07) 12(53.34,52.07) 13(50.8,52.07) 14(48.26,52.07) 15(45.72,52.07) 16(43.18,52.07) 17(40.64,52.07) 18(38.1,52.07) 19(35.56,52.07) 20(33.02,52.07) 21(33.02,8.89) 22(35.56,8.89) 23(38.1,8.89) 24(40.64,8.89) 25(43.18,8.89) 26(45.72,8.89) 27(48.26,8.89) 28(50.8,8.89) 29(53.34,8.89) 30(55.88,8.89) 31(55.88,49.53) 32(53.34,49.53) 33(50.8,49.53) 34(48.26,49.53) 35(45.72,49.53) 36(43.18,49.53) 37(40.64,49.53) 38(38.1,49.53) 39(35.56,49.53) 42(99.06,6.35) 43(101.6,6.35) 44(104.14,6.35) 45(106.68,6.35) 46(109.22,6.35) 47(111.76,6.35) 48(114.3,6.35) 49(116.84,6.35) 50(119.38,6.35) 51(119.38,52.07) 52(116.84,52.07) 53(114.3,52.07) 54(111.76,52.07) 55(109.22,52.07) 56(106.68,52.07) 57(104.14,52.07) 58(101.6,52.07) 59(99.06,52.07) 60(96.52,52.07) 61(96.52,8.89) 62(99.06,8.89) 63(101.6,8.89) 64(104.14,8.89) 65(106.68,8.89) 66(109.22,8.89) 67(111.76,8.89) 68(114.3,8.89) 69(116.84,8.89) 70(119.38,8.89) 71(119.38,49.53) 72(116.84,49.53) 73(114.3,49.53) 74(111.76,49.53) 75(109.22,49.53) 76(106.68,49.53) 77(104.14,49.53) 78(101.6,49.53) 79(99.06,49.53)
  silkscreen extent 0,0 131,58.5, body extent 0,0 130.85,58.42, height 13.81
LED_SMD_1206 [mil]
  rect 60x85 smd: 1(-60,0) 2(60,0)
  silkscreen extent -110,-53 100,53, body extent -63,-32 63,31, height 44
LTC1992 [mil]
  rect 61.5x17 smd paste+0 mask+0: 1(-91.75,38.39) 2(-91.75,12.8) 3(-91.75,-12.8) 4(-91.75,-38.39) 5(91.75,-38.39) 6(91.75,-12.8) 7(91.75,12.8) 8(91.75,38.39)
  silkscreen extent -95,-66 66,66, body extent -101,-61 101,61, height 43
MAX91XX [mil]
  rect 62.5x14 smd paste+0 mask+0: 1(-119.75,89.57) 2(-119.75,63.98) 3(-119.75,38.39) 4(-119.75,12.8) 5(-119.75,-12.8) 6(-119.75,-38.39) 7(-119.75,-63.98) 8(-119.75,-89.57) 9(119.75,-89.57) 10(119.75,-63.98) 11(119.75,-38.39) 12(119.75,-12.8) 13(119.75,12.8) 14(119.75,38.39) 15(119.75,63.98) 16(119.75,89.57)
  silkscreen extent -125,-106 171,120, body extent -129,-101 129,101, height 43
REG_TH_3P_2.54 [mil]
  rect 65x65 hole 40: 1(-100,-11.81)
  round 65 hole 40: 2(0,-11.81) 3(100,-11.81)
  silkscreen extent -205,-157 200,206, body extent -205,-157 205,181, height 634
RESIS_SMD_1206 [mil]
  rect 60x80 smd: 1(-60,0) 2(60,0)
  silkscreen extent -102,-52 102,52, body extent -63,-31 63,31, height 30
TACTILE-TH-4PIN [mil]
  oct 120x60 hole 39.37: 1(-128,89) 2(-128,-89) 3(128,89) 4(128,-89)
  silkscreen extent -130,-127 130,127, body extent -152,-118 152,118, height 197

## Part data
+3.3V +5V +15V -15V LED6 LED_0 LED_1 LED_2 LED_3: library part LED, "LED", Manufacturer_Name=Vishay
C1_1 C2_1 C2_2 C2_3 C2_4 C3 C4 C5 C6 C8 C9 C10 C11 C12 C14 C16 C17 C18 C19 C20 C22 C23 C24 C25 C26 C27 C28 C29 C30 C31 C32 C33 C34 C35 C36 C37 C38 C39 C40 C41 C42 C43 C44 Cn_1 Cn_2 Cn_3 Cn_4 Cp_1 Cp_2 Cp_3 Cp_4: "Capacitor", Manufacturer_Name=Kemet, Manufacturer_Part_Number=C1206X475K3RACAUTO7210, Mouser Part Number=80-C1206X475K3RAUTLR
D1 D2: library part Diode, "Diode", Manufacturer_Name=Vishay
IC1 IC3: library part Regulador_3.3_1.5, "Power Supply", Arrow Part Number=OKI-78SR-3.3/1.5-W36-C, Manufacturer_Name="Murata Electronics", Mouser Part Number=580-OKI78SR3.31.536C
IC2 IC4: library part ADP7118ARDZ-5.0, "Power Supply", Manufacturer_Name="Analog Devices", Mouser Part Number=584-ADP7118ARDZ-5.0
IC5 IC7: "No Description Available", Manufacturer_Part_Number=MAX9123EUE+, Mfr_Name="Maxim Integrated Products"
IC6 IC8: library part MAX9121/22, "No Description Available", Manufacturer_Part_Number=MAX9122EUE+, Mfr_Name="Maxim Integrated Products"
IC9 IC10 IC11 IC12: "No Description Available", Manufacturer_Part_Number=LTC1992IMS8#PBF, Mfr_Name="Analog Devices / Linear Technology"
IC13 IC14: library part LM339, "Integrated Circuit", Manufacturer_Name="Texas Instruments", Mouser Part Number=595-LM339AN
IC15: library part 7404_Not, "Integrated Circuit", Arrow Part Number=LM339AN, Manufacturer_Name="Texas Instruments", Mouser Part Number=595-LM339AN
IC16: library part SN7408, "Integrated Circuit", Manufacturer_Name="Texas Instruments", Mouser Part Number=595-SN7400N
IC17: library part NE555, "Integrated Circuit", Manufacturer_Name=ST, Mouser Part Number=N/A
J1: library part Con_4Pin_Horizontal_Plugin_3.5mm, "No Description Available", Mfr_Name="TE Connectivity"
J2 J3 J9 J10 J21 J22: library part Con_Header_3P, "Connector", Manufacturer_Name=Molex, Mouser Part Number=538-22-27-2031
J4: library part Con_Header_14P, "Connector dual row"
J5 J6: library part Con_Ethernet_2x1, "No Description Available", Mfr_Name="TE Connectivity"
J7 J8: library part Con_Header_8P_2R, "No Description Available", Mfr_Name="TE Connectivity"
J11: "DB9 (Right angle  PCB mount)", ASiD Part Number=DB9-AS
J12 J13: library part Con_BNC_Vertical_5-1634503-1, "No Description Available", Mfr_Name="TE Connectivity"
J14 J15 J16 J17: "Connector", Arrow Part Number=TRAPC4M1X, Manufacturer_Name=Switchcraft, Mouser Part Number=502-TRAPC4M1X
J18: library part Con_5Pin_Horizontal_plugin_3.5mm, "Conector 5 Pinos 3.5mm", Mfr_Name="TE Connectivity"
J19: library part Con_10Pin_Horizontal_plugin_3.50mm, "No Description Available", Mfr_Name="TE Connectivity"
J20: "LaunchPad F28379D"
R1_1 R1_2 R1_3 R1_4 R2 R2_1 R2_2 R2_3 R2_4 R3 R3_1 R3_2 R3_3 R3_4 R4 R4_1 R4_2 R4_3 R4_4 R5 R5_1 R6 R6_1 R7 R8 R9 R10 R11 R12 R13 R14 R15 R16 R17 R18 R19 R20 R21 R22 R23 R24 Rm_1 Rm_2 Rm_3 Rm_4 Rn1_1 Rn1_2 Rn1_3 Rn1_4 Rn2_1 Rn2_2 Rn2_3 Rn2_4 Rp1_1 Rp1_2 Rp1_3 Rp1_4 Rp2_1 Rp2_2 Rp2_3 Rp2_4 Rs_1 Rs_2 Rs_3 Rs_4: library part Resistor, "Resistor"
S1 S2: library part Button, "Switch", Manufacturer_Name="TE Connectivity", Mouser Part Number=N/A
T1 T2 T3 T4: library part Con_Header_2P, "Connector", Manufacturer_Name="CUI Devices", Mouser Part Number=490-TB004-508-02BE

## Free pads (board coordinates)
  round 354.33 hole 177.17 mask+39.37: 1(5450,3050) 1(5450,9300) 1(7950,3050) 1(7950,9300) 1(10175,3050) 1(10175,9275)

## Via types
v1: diameter 35, hole 15, Top Layer to Bottom Layer, tented both sides, 433 vias
v2: diameter 35, hole 15, Top Layer to Bottom Layer, tented top, 166 vias
v3: diameter 26, hole 10, Top Layer to Bottom Layer, tented top, 146 vias
v4: diameter 26, hole 10, Top Layer to Bottom Layer, tented both sides, 1 vias

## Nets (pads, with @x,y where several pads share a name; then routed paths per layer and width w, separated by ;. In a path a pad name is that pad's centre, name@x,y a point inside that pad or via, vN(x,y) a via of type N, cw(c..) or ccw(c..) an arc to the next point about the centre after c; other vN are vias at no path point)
3V3: C14.1 C23.1 C24.1 C25.1 C26.1 C27.1 C28.1 C29.1 C30.1 C43.1 C44.1 IC5.1 IC5.4 IC6.13 IC6.16 IC7.1 IC7.4 IC8.13 IC8.16 IC9.3 IC10.3 IC11.3 IC12.3 J2.2 J20.1 J20.41 R5.1 R5_1.1 R22.2 R24.2 | length 3064.8
  Top Layer w15: IC11.3@6049.41,4850 v3(6049.41,4924.41) ; IC9.3@6049.41,7350 v3(6049.41,7424.41) ; IC12.3@6050,4225 v3(6050,4300) ; IC10.3@6050,6725 v3(6050,6800) ; v3(6275,3450) 6275,3275 6295,3255 R22.2@6350,3255 ; v3(6725,3450) 6725,3275 6745,3255 R24.2@6800,3255 ; J20.41@6725,5175 C44.1@6725,5325 ; J20.1@6725,7675 C43.1@6725,7825 ; v3(9220.87,7529.13) IC5.1@9285.5,7529.13 ; v3(9275,5225) C25.1@9350,5225 9350,5070 9331.77,5051.77 IC7.4@9285.5,5051.77 ; v3(9275,7625) C23.1@9350,7625 9350,7475 9327.36,7452.36 IC5.4@9285.5,7452.36 ; IC7.1@9285.5,5128.54 v3(9285.5,5164.5)
  Top Layer w25: R5.1@7250,3375 v2(7250,3450) ; C14.1@8100,3450 v2(8100,3525)
  Bottom Layer w15: v3(6049.41,4924.41) 6049.41,4999.41 C29.1@6050,5000 ; v3(6049.41,7424.41) 6049.41,7499.41 C27.1@6050,7500 ; v3(6050,4300) C30.1@6050,4375 ; v3(6050,6800) C28.1@6050,6875 ; R5_1.1@6075,6250 v3(6075,6350) ; v3(9229.13,7129.13) IC6.16@9285.5,7129.13 ; v3(9275,4825) C26.1@9350,4825 9350,4670 9331.77,4651.77 IC8.13@9285.5,4651.77 ; v3(9275,7225) C24.1@9350,7225 9350,7070 9332.36,7052.36 IC6.13@9285.5,7052.36 ; IC8.16@9285.5,4728.54 v3(9285.5,4764.5)
3V3_ADP: C12.1 IC2.1 IC2.2 IC2.3 J2.1 | length 350
  Top Layer w25: J2.1@8250,3550 C12.1@8400,3550 IC2.1@8400,3450 IC2.2@8400,3400 IC2.3@8400,3350
3V3_OKI: C9.1 IC1.3 J2.3 | length 425
  Top Layer w25: J2.3@8250,3350 C9.1@8250,3100 IC1.3@8425,3100
5V0: C22.1 C37.1 C38.1 C39.1 D1.1 IC15.14 IC16.14 IC17.8 J1.4 J3.2 J10.1 R4.1 R16.2 R18.2 R20.2 | length 3477.7
  Top Layer w15: v3(5675,8200) R16.2@5775,8200 ; R20.2@5900,8450 v3(5975,8450) ; R18.2@5900,8600 v3(5975,8600) ; v3(6025,8875) J10.1@6125,8875 ; IC17.8@6350,8225 C39.1@6575,8225 v3(6575,8300) ; IC16.14@6350,8700 6400,8700 6450,8750 C38.1@6450,8875 v3(6450,8975) ; IC15.14@6800,8700 C37.1@6800,8875 v3(6800,8975)
  Top Layer w25: R4.1@7375,3375 7375,3595.25 7461.13,3681.38 9038.66,3681.38 v2(9107.28,3750) C22.1@9107.28,3850
  Bottom Layer w15: D1.1@6965.35,7950 v3(6965.35,8040.35)
5V0_ADP: C20.1 IC4.1 IC4.2 IC4.3 J3.1 | length 350
  Top Layer w25: J3.1@9175,3550 C20.1@9325,3550 IC4.1@9325,3450 IC4.2@9325,3400 IC4.3@9325,3350
5V0_OKI: C17.1 IC3.3 J3.3 | length 425
  Top Layer w25: J3.3@9175,3350 C17.1@9175,3100 IC3.3@9350,3100
+15V0: C5.1 C6.1 C33.1 C35.1 IC13.3 IC14.3 J1.2 J14.1 J15.1 J16.1 J17.1 R3.1 R6.1 R7.2 R8.1 R9.2 R14.2 Rp1_1.2 Rp1_2.2 Rp1_3.2 Rp1_4.2 | length 1535.8
  Top Layer w25: R3.1@7625,3375 v2(7625,3450) ; R6.1@8920,3100 v2(8975,3100) ; R7.2@8920,3225 v2(8975,3225) ; C5.1@9550,3835 v2(9550,3925) ; C6.1@9725,3825 v2(9725,3925) ; R8.1@9845,3100 v2(9900,3100) ; R9.2@9845,3225 v2(9900,3225)
  Bottom Layer w15: v3(6295,3855) Rp1_4.2@6295,3950 ; v3(6295,6355) Rp1_2.2@6295,6450 ; v3(6425,7875) Rp1_1.2@6425,7925 R14.2@6550,7925 ; v3(6475,4325) C35.1@6425,4325 6425,4375 6500,4450 IC14.3@6500,4515 ; v3(6475,5400) 6500,5400 6545,5355 Rp1_3.2@6545,5300 ; v3(6475,6825) C33.1@6425,6825 6425,6875 6500,6950 IC13.3@6500,7015
  other v2: 6225,2950 6225,3025 6300,3025 6225,3100 6225,3190 6300,3190 6225,3275 6210,3590 6260,3590 6310,3590
-15V0: -15V.1 C3.2 C4.2 C34.2 C36.2 IC13.12 IC14.12 J1.3 J14.2 J15.2 J16.2 J17.2 Rn1_1.2 Rn1_2.2 Rn1_3.2 Rn1_4.2 | length 1575.1
  Top Layer w25: v2(7500,2950) -15V.1@7500,3030 ; v2(9550,4075) C3.2@9550,4200 ; v2(9725,4075) C4.2@9725,4200
  Bottom Layer w15: Rn1_3.2@6295,5300 6295,5395 6375,5475 v3(6425,5475) ; Rn1_1.2@6295,7800 v3(6295,8020) ; v3(6475,4925) C36.2@6425,4925 6425,4875 6500,4800 IC14.12@6500,4735 ; v3(6475,7425) C34.2@6425,7425 6425,7375 6500,7300 IC13.12@6500,7235 ; Rn1_4.2@6545,3950 6545,3880 v3(6575,3850) ; Rn1_2.2@6545,6450 6545,6380 v3(6575,6350)
  other v2: 6450,2775 6500,2775 6550,2775 6500,2825 6550,2825 6500,2875 6550,2875 6450,3590 6500,3590 6550,3590
/Enable: IC15.4 J22.1 | length 856.8
  Top Layer w15: v3(6500,8550) IC15.4@6580,8550
  Bottom Layer w15: J22.1@6125,9025 6125,8975 6150,8950 6350,8950 6400,8900 6400,8600 6450,8550 v3(6500,8550)
ADC-B2: J19.5 J20.28 | length 3496.1
  Bottom Layer w15: J20.28@6825,6975 6875,6925 7024.62,6925 7095.78,6996.16 7095.78,7154.22 8940.03,8998.46 8940.03,9126.05 J19.5@9138.98,9325
ADC-B3: J19.8 J20.25 | length 2910.6
  Bottom Layer w15: J20.25@6825,7275 6950.2,7275 8654.65,8979.46 8654.65,9254.06 J19.8@8725.59,9325
ADC-B4: J20.68
ADC-B5: J20.65
ADC-d1: IC13.5 IC13.6 R1_2.2 Rm_2.1 Rs_2.2 T2.1 | length 1131.1
  Top Layer w15: R1_2.2@5725,6600 Rs_2.2@5725,6755 Rm_2.1@5850,6755 v3(5945,6755)
  Bottom Layer w15: v3(5945,6755) 6055,6755 6125,6825 6125,6975 T2.1@6200,7050 6250,7100 6325,7100 6350,7075 IC13.6@6350,7015 IC13.5@6400,7015
ADC-d1N: IC10.5 J20.26 R4_2.2 | length 1070.7
  Top Layer w15: R4_2.2@6075,7050 6075.59,7049.41 IC10.5@6075.59,6908.5 6116.5,6908.5 6200,6825 6249.57,6825 6449.57,7025 6600,7025 v3(6650,7074.98)
  Bottom Layer w15: v3(6650,7074.98) 6700,7124.96 ; 6700,7124.98 6774.98,7124.98 J20.26@6825,7175
ADC-d1P: IC10.4 J20.29 R2_2.1 | length 1040.3
  Top Layer w15: R2_2.1@6075,6600 6075.59,6600.59 IC10.4@6075.59,6725 6125,6725 6200,6800 6259.93,6800 6459.93,7000 6600,7000 6675,6925 6775,6925 J20.29@6825,6875
ADC-d2: IC14.5 IC14.6 R1_4.2 Rm_4.1 Rs_4.2 T4.1 | length 1131.1
  Top Layer w15: R1_4.2@5725,4100 Rs_4.2@5725,4255 Rm_4.1@5850,4255 v3(5945,4255)
  Bottom Layer w15: v3(5945,4255) 6055,4255 6125,4325 6125,4475 T4.1@6200,4550 6250,4600 6325,4600 6350,4575 IC14.6@6350,4515 IC14.5@6400,4515
ADC-d2N: IC12.5 J20.66 R4_4.2 | length 1070.7
  Top Layer w15: R4_4.2@6075,4550 6075.59,4549.41 IC12.5@6075.59,4408.5 6116.5,4408.5 6200,4325 6250.79,4325 6450.79,4525 6600,4525 v3(6650,4575)
  Bottom Layer w15: v3(6650,4575) 6651.63,4575 6701.63,4625 6775,4625 J20.66@6825,4675
ADC-d2P: IC12.4 J20.69 R2_4.1 | length 1040.3
  Top Layer w15: R2_4.1@6075,4100 6075.59,4100.59 IC12.4@6075.59,4225 6125,4225 6200,4300 6265.55,4300 6465.55,4500 6600,4500 6675,4425 6775,4425 J20.69@6825,4375
ADC-d4N: J20.63
ADC-d4P: J20.23
ADC-d5: IC14.9 IC14.10 R1_3.2 Rm_3.1 Rs_3.2 T3.1 | length 995.6
  Top Layer w15: R1_3.2@5725,4725 Rs_3.2@5725,4880 Rm_3.1@5850,4880 v3(5945,4880)
  Bottom Layer w15: v3(5945,4880) 6020,4880 T3.1@6200,4700 6250,4650 6325,4650 6350,4675 IC14.9@6350,4735 IC14.10@6400,4735
ADC-d5N: IC11.5 J20.64 R4_3.2 | length 1061.1
  Top Layer w15: R4_3.2@6075,5175 6075.5,5174.5 6075.5,5034 IC11.5@6075,5033.5 6116.5,5033.5 6200,4950 6271.42,4950 6471.42,4750 6600,4750 6675,4825 6775,4825 J20.64@6825,4875
ADC-d5P: IC11.4 J20.67 R2_3.1 | length 1051
  Top Layer w15: R2_3.1@6075,4725 IC11.4@6075,4850 6125,4850 6200,4925 6254.06,4925 6454.06,4725 6599,4725 6699,4625 6775,4625 J20.67@6825,4575
ADC-d6: IC13.9 IC13.10 R1_1.2 Rm_1.1 Rs_1.2 T1.1 | length 970.6
  Top Layer w15: R1_1.2@5725,7250 Rs_1.2@5725,7380 Rm_1.1@5850,7380 v3(5945,7380)
  Bottom Layer w15: v3(5945,7380) 6020,7380 T1.1@6200,7200 6250,7150 6325,7150 6350,7175 IC13.9@6350,7235 IC13.10@6400,7235
ADC-d6N: IC9.5 J20.24 R4_1.2 | length 1061.1
  Top Layer w15: R4_1.2@6075,7675 6075.5,7674.5 6075.5,7534 IC9.5@6075,7533.5 6116.5,7533.5 6200,7450 6260.36,7450 6460.36,7250 6600,7250 6675,7325 6775,7325 J20.24@6825,7375
ADC-d6P: IC9.4 J20.27 R2_1.1 | length 1051
  Top Layer w15: R2_1.1@6075,7225 IC9.4@6075,7350 6125,7350 6200,7425 6250,7425 6450,7225 6600,7225 6700,7125 6775,7125 J20.27@6825,7075
B_MCLK+: IC7.10 J6.A7 | length 439.8
  Top Layer w15: IC7.10@9525,4975 9592.68,4975 9777.52,4790.16 J6.A7@9888.19,4790.16
B_MCLK-: IC7.9 J6.A8 | length 549.8
  Top Layer w15: IC7.9@9525,4949.41 9575.59,4949.41 9779.9,4745.1 9983.29,4745.1 J6.A8@9988.19,4750
B_MI+: IC8.3 J6.A3 | length 1011.9
  Top Layer w15: v3(9611.32,4677.36) 9640.83,4677.36 9640.83,4676.65 9692.48,4625 10001.57,4625 10075,4698.43 10075,4900 10024.21,4950.79 J6.A3@9888.19,4950.79
  Bottom Layer w15: IC8.3@9525,4677.36 v3(9611.32,4677.36)
B_MI-: IC8.4 J6.A6 | length 699.6
  Top Layer w15: v3(9701.77,4651.77) 9992.98,4651.77 10050,4708.79 10050,4775 9994.68,4830.31 J6.A6@9988.19,4830.31
  Bottom Layer w15: IC8.4@9525,4651.77 v3(9701.77,4651.77)
B_MO+: IC7.11 J6.A5 | length 417.1
  Top Layer w15: IC7.11@9525,5000.59 9685.31,5000.59 9815.43,4870.47 J6.A5@9888.19,4870.47
B_MO-: IC7.12 J6.A4 | length 511.1
  Top Layer w15: IC7.12@9525,5026.18 9695.08,5026.18 9810.63,4910.63 J6.A4@9988.19,4910.63
B_MSS+: IC7.15 J6.A1 | length 412.7
  Top Layer w15: IC7.15@9525,5102.95 9850,5102.95 9888.19,5064.76 J6.A1@9888.19,5031.1
B_MSS-: IC7.16 J6.A2 | length 541.3
  Top Layer w15: IC7.16@9525,5128.54 9886.71,5128.54 9988.19,5027.07 J6.A2@9988.19,4990.94
B_SCLK+: IC8.7 J6.B7 | length 1407
  Bottom Layer w15: IC8.7@9525,4575 9591.7,4575 9636.04,4530.66 10347.11,4530.66 10398.08,4581.63 10398.08,4883.43 10290.68,4990.83 10250.11,4990.83 J6.B7@10250,4990.94
B_SCLK-: IC8.8 J6.B8 | length 1604.7
  Bottom Layer w15: IC8.8@9525,4549.41 9573.51,4549.41 9617.26,4505.66 10357.46,4505.66 10423.08,4571.28 10423.08,4901.92 10289,5036 10154.9,5036 J6.B8@10150,5031.1
B_SI+: IC8.6 J6.B5 | length 1118.1
  Bottom Layer w15: IC8.6@9525,4600.59 9785.95,4600.59 9810.36,4625 10285.36,4625 10325,4664.64 10325,4860.36 10282.4,4902.95 10257.68,4902.95 J6.B5@10250,4910.63
B_SI-: IC8.5 J6.B4 | length 1128.7
  Bottom Layer w15: IC8.5@9525,4626.18 9776.18,4626.18 9800,4650 10275,4650 10300,4675 10300,4850 10279.53,4870.47 J6.B4@10150,4870.47
B_SO+: IC7.14 J6.B3 | length 931.8
  Top Layer w15: IC7.14@9525,5077.36 v3(9697.64,5077.36)
  Bottom Layer w15: v3(9697.64,5077.36) 9721.44,5101.16 9973.84,5101.16 10050,5025 10050,4880.31 10100,4830.31 J6.B3@10250,4830.31
B_SO-: IC7.13 J6.B6 | length 774.2
  Top Layer w15: IC7.13@9525,5051.77 v3(9601.77,5051.77)
  Bottom Layer w15: v3(9601.77,5051.77) 9603.88,5053.88 9636.85,5053.88 9709.14,5126.16 9998.84,5126.16 10075,5050 10075,4975 10100,4950 10149.21,4950 J6.B6@10150,4950.79 J6.B6@10150.79,4950
B_SSS+: IC8.2 J6.B1 | length 767.6
  Bottom Layer w15: IC8.2@9525,4702.95 9772.05,4702.95 9800,4675 10125,4675 10200,4750 J6.B1@10250,4750
B_SSS-: IC8.1 J6.B2 | length 706.3
  Bottom Layer w15: IC8.1@9525,4728.54 9781.81,4728.54 9810.36,4700 10114.64,4700 10150,4735.36 J6.B2@10150,4790.16
Button_Enable: J18.3 R17.2 | length 200
  Top Layer w15: J18.3@5450,8600 R17.2@5650,8600
Button_Reset: J18.5 R19.2 | length 252.4
  Top Layer w15: J18.5@5450,8324.41 5450,8325 5575,8450 R19.2@5650,8450
DAC1: J20.32
DAC2: J20.31
DAC3: J20.72
DAC4: J20.71
DAC-A: J12.1 J20.30 | length 2037.1
  Top Layer w15: J12.1@5350,6125 5350,6425 5425,6500 6750,6500 6825,6575 J20.30@6825,6775
DAC-B: J13.1 J20.70 | length 1947.6
  Bottom Layer w15: J13.1@5350,3625 5500,3625 5647.48,3772.48 6669.56,3772.48 6825,3927.92 J20.70@6825,4275
Driver_Enable: J11.2 J22.2 | length 4256.4
  Top Layer w15: J22.2@6225,9025 6225,9075 6250,9100 7700.25,9100 8550.25,8250 J11.2@10069,8250
Enable: IC15.3 IC16.11 J21.3 J22.3 | length 1682.8
  Top Layer w15: J22.3@6325,9025 6650,9025 6700,8975 6700,8650 6650,8600 IC15.3@6580,8600 6450,8600 6400,8550 IC16.11@6350,8550
  Bottom Layer w15: J21.3@5875,9025 5875,9075 5900,9100 6300,9100 6325,9075 J22.3@6325,9025
Enable_DSC: IC16.2 J20.2 | length 1582.1
  Top Layer w15: IC16.2@6130,8650 v3(6200,8650) ; v3(6225,8025) 6225,7700 6350,7575 J20.2@6725,7575
  Bottom Layer w15: v3(6200,8650) 6225,8625 v3(6225,8025)
Error_ADC: IC13.1 IC13.2 IC13.13 IC13.14 IC14.1 IC14.2 IC14.13 IC14.14 R14.1 R15.1 | length 3687.1
  Bottom Layer w15: IC14.2@6550,4515 IC14.1@6600,4515 IC14.14@6600,4735 ; IC14.13@6550,4735 IC14.14@6600,4735 ; IC13.2@6550,7015 IC13.1@6600,7015 ; IC13.13@6550,7235 IC13.14@6600,7235 ; R14.1@6550,7805 R15.1@6675,7805 6675,7750 6646.94,7721.94 6646.94,7346.94 6600,7300 IC13.14@6600,7235 ; IC14.14@6600,4735 6600,4800 6649.5,4849.5 6649.5,6900.5 6600,6950 IC13.1@6600,7015 ; IC13.1@6600,7015 IC13.14@6600,7235
ERROR_ADC_0V: IC15.6 IC17.4 | length 665.4
  Top Layer w15: IC17.4@6130,8075 6224.97,8075 6252.02,8102.05 6252.02,8204.64 6497.38,8450 IC15.6@6580,8450
Error_Enable: IC17.3 J10.3 LED6.1 | length 1203.2
  Top Layer w15: LED6.1@5895,8200 v3(5975,8200) 6050,8125 IC17.3@6130,8125
  Bottom Layer w15: v3(5975,8200) 6025,8250 6025,8700 6100,8775 6300,8775 6325,8800 J10.3@6325,8875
